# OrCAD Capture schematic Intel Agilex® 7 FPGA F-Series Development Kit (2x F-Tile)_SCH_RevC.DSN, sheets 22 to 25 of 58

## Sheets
22 PG22 AGX HPS, TEMPDIODE, DNU: size C
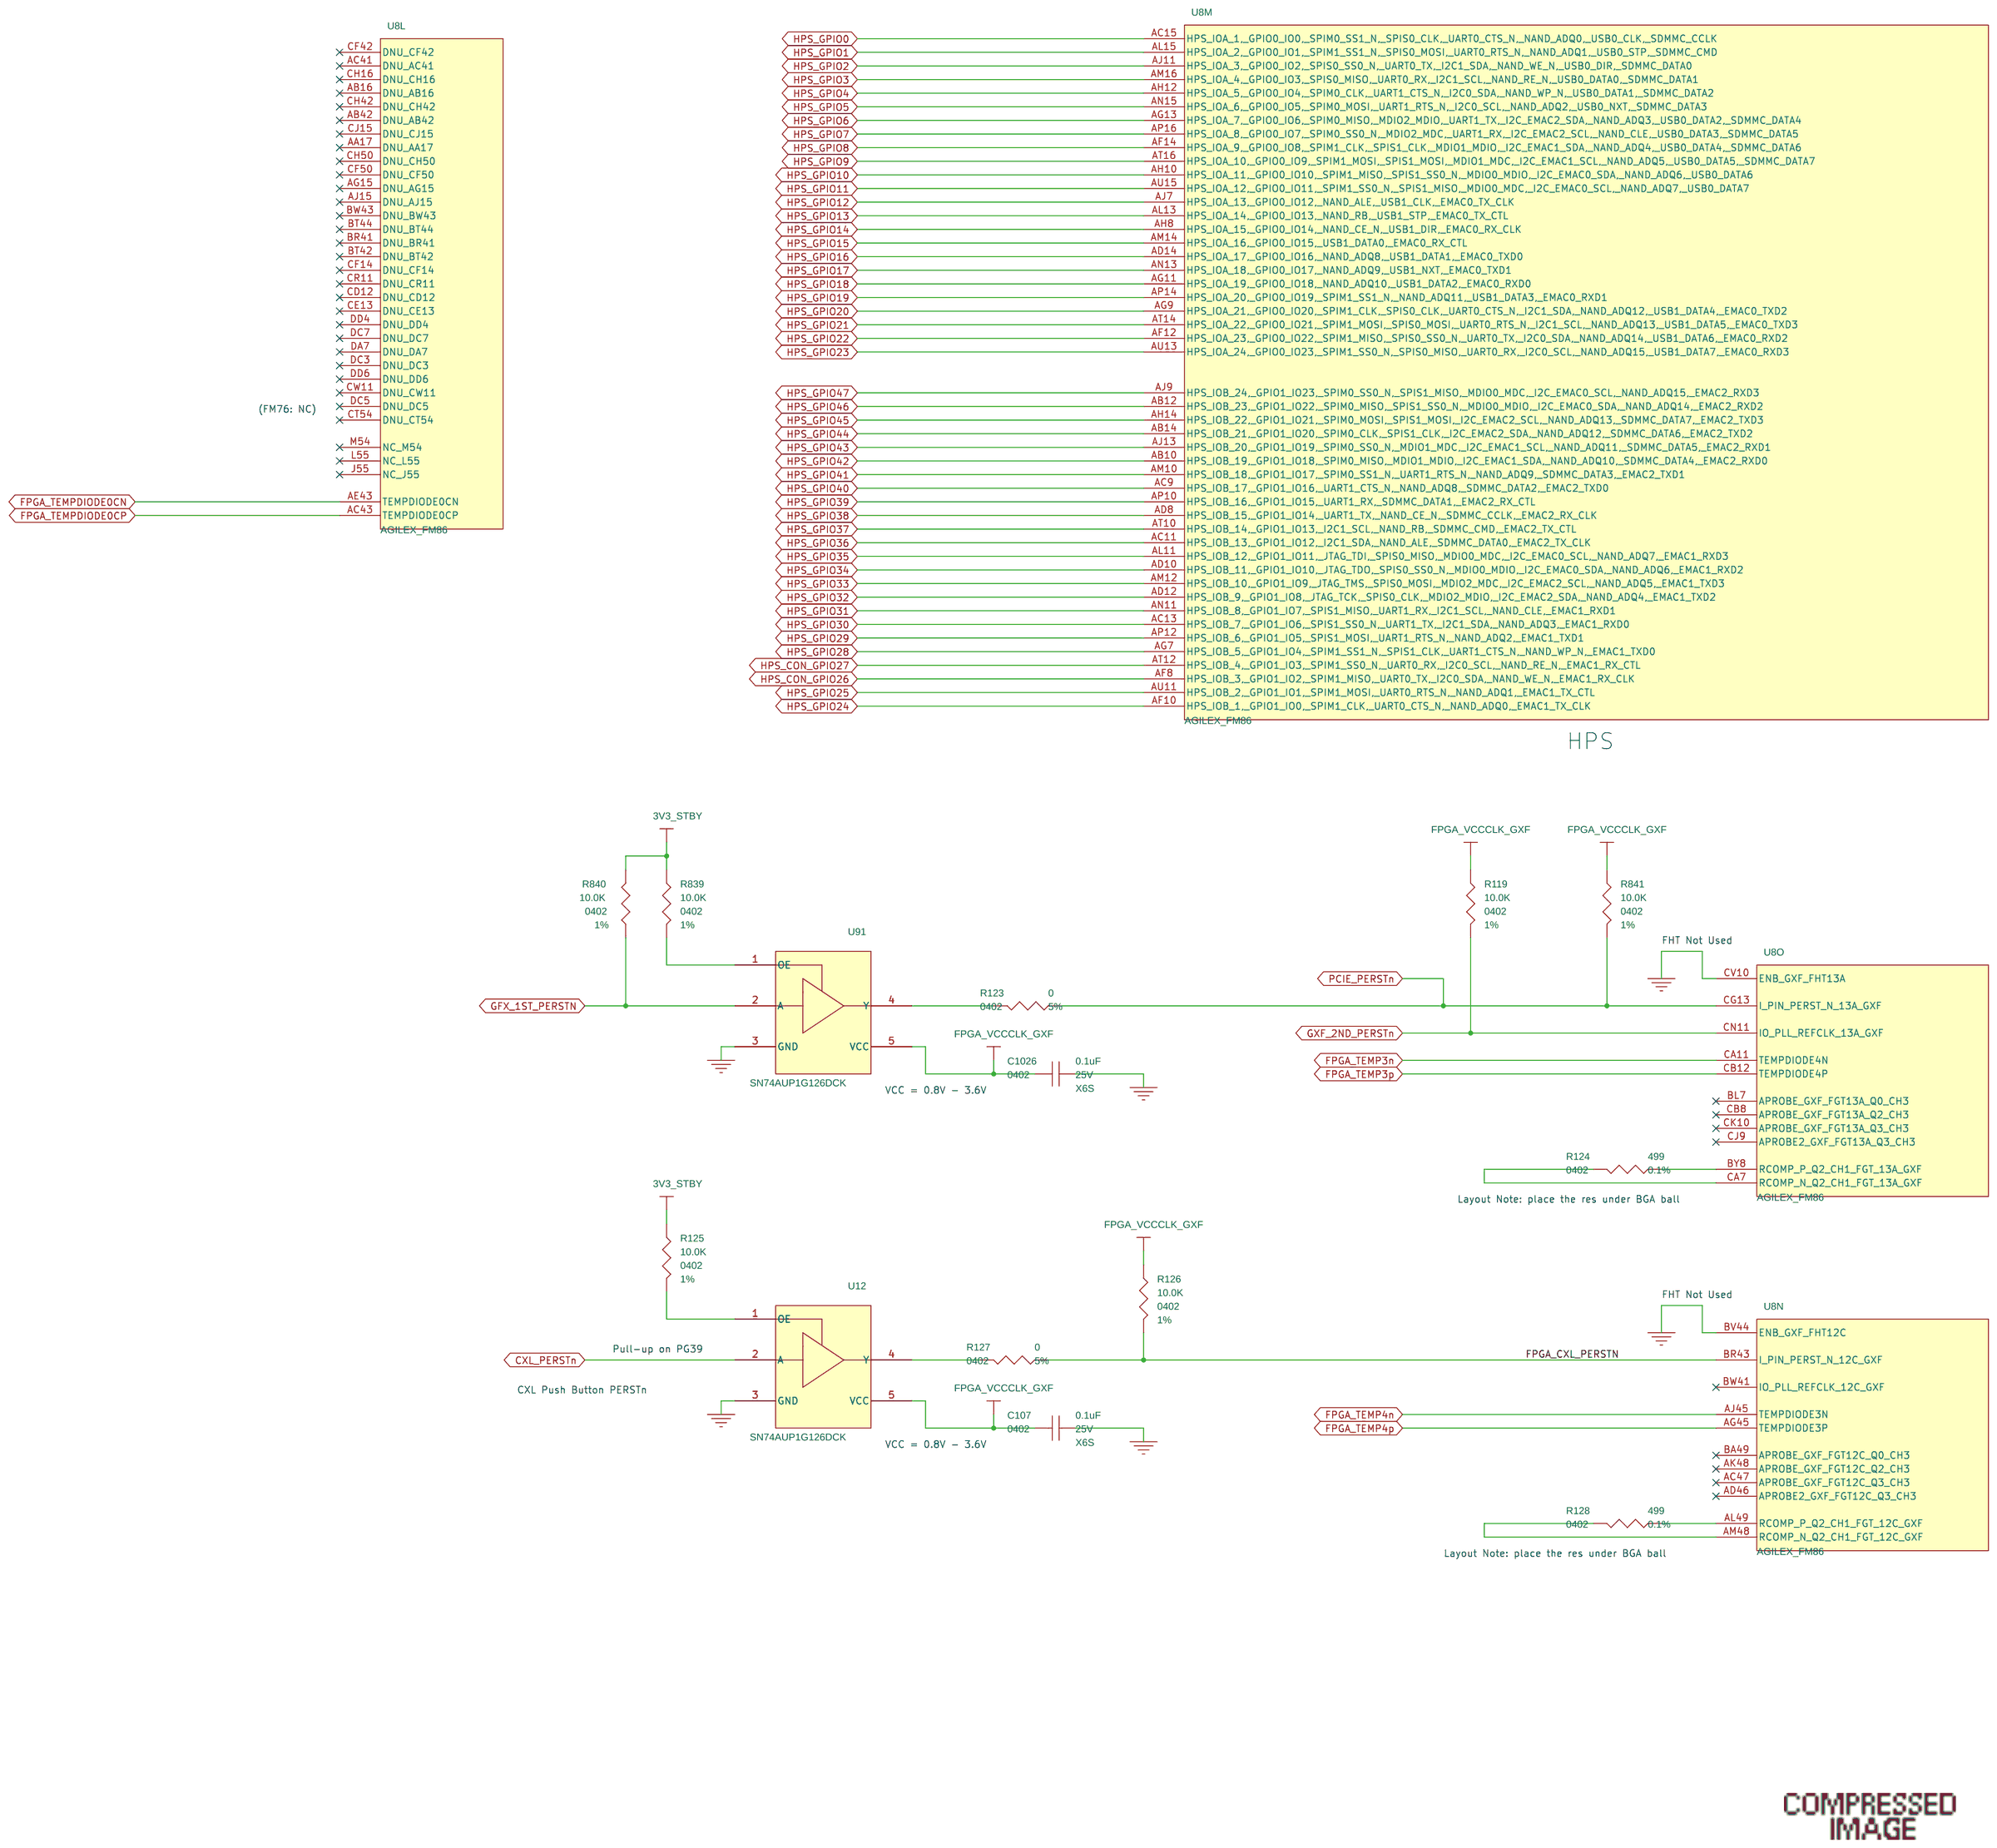
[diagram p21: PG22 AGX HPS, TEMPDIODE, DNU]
23 PG23 AGX POWER: size C
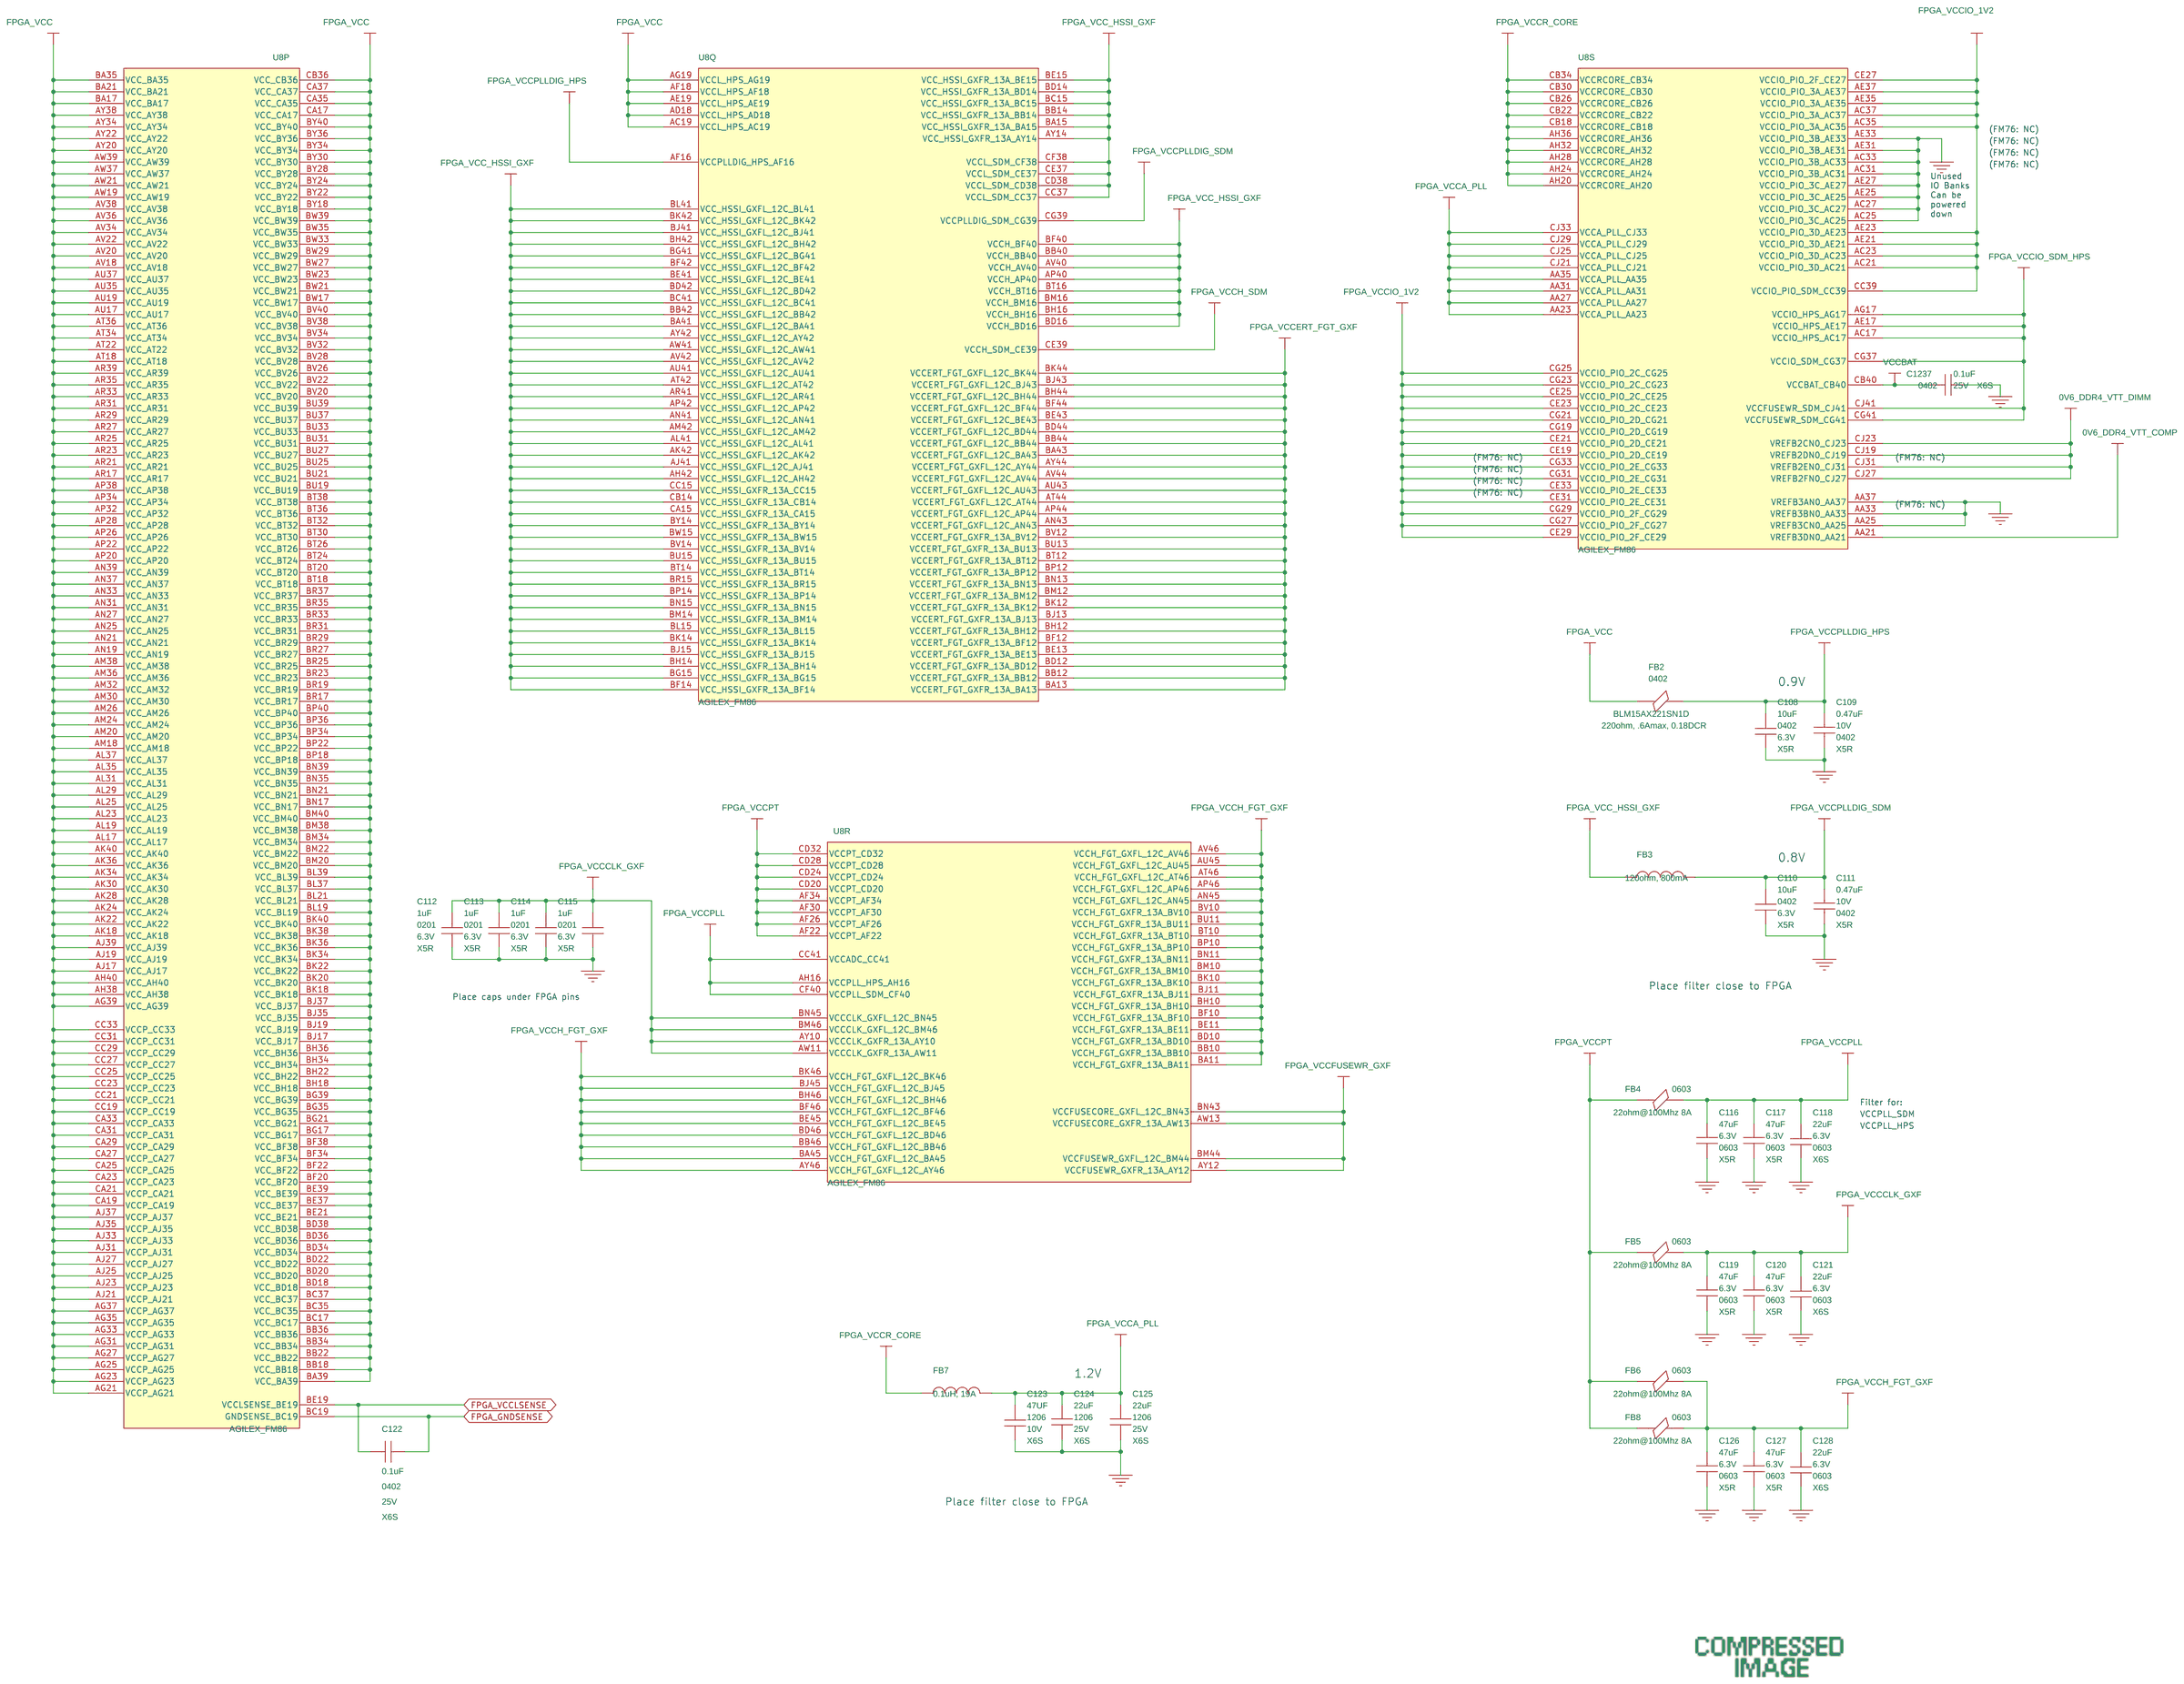
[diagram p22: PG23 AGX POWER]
24 PG24 AGX GND: size C
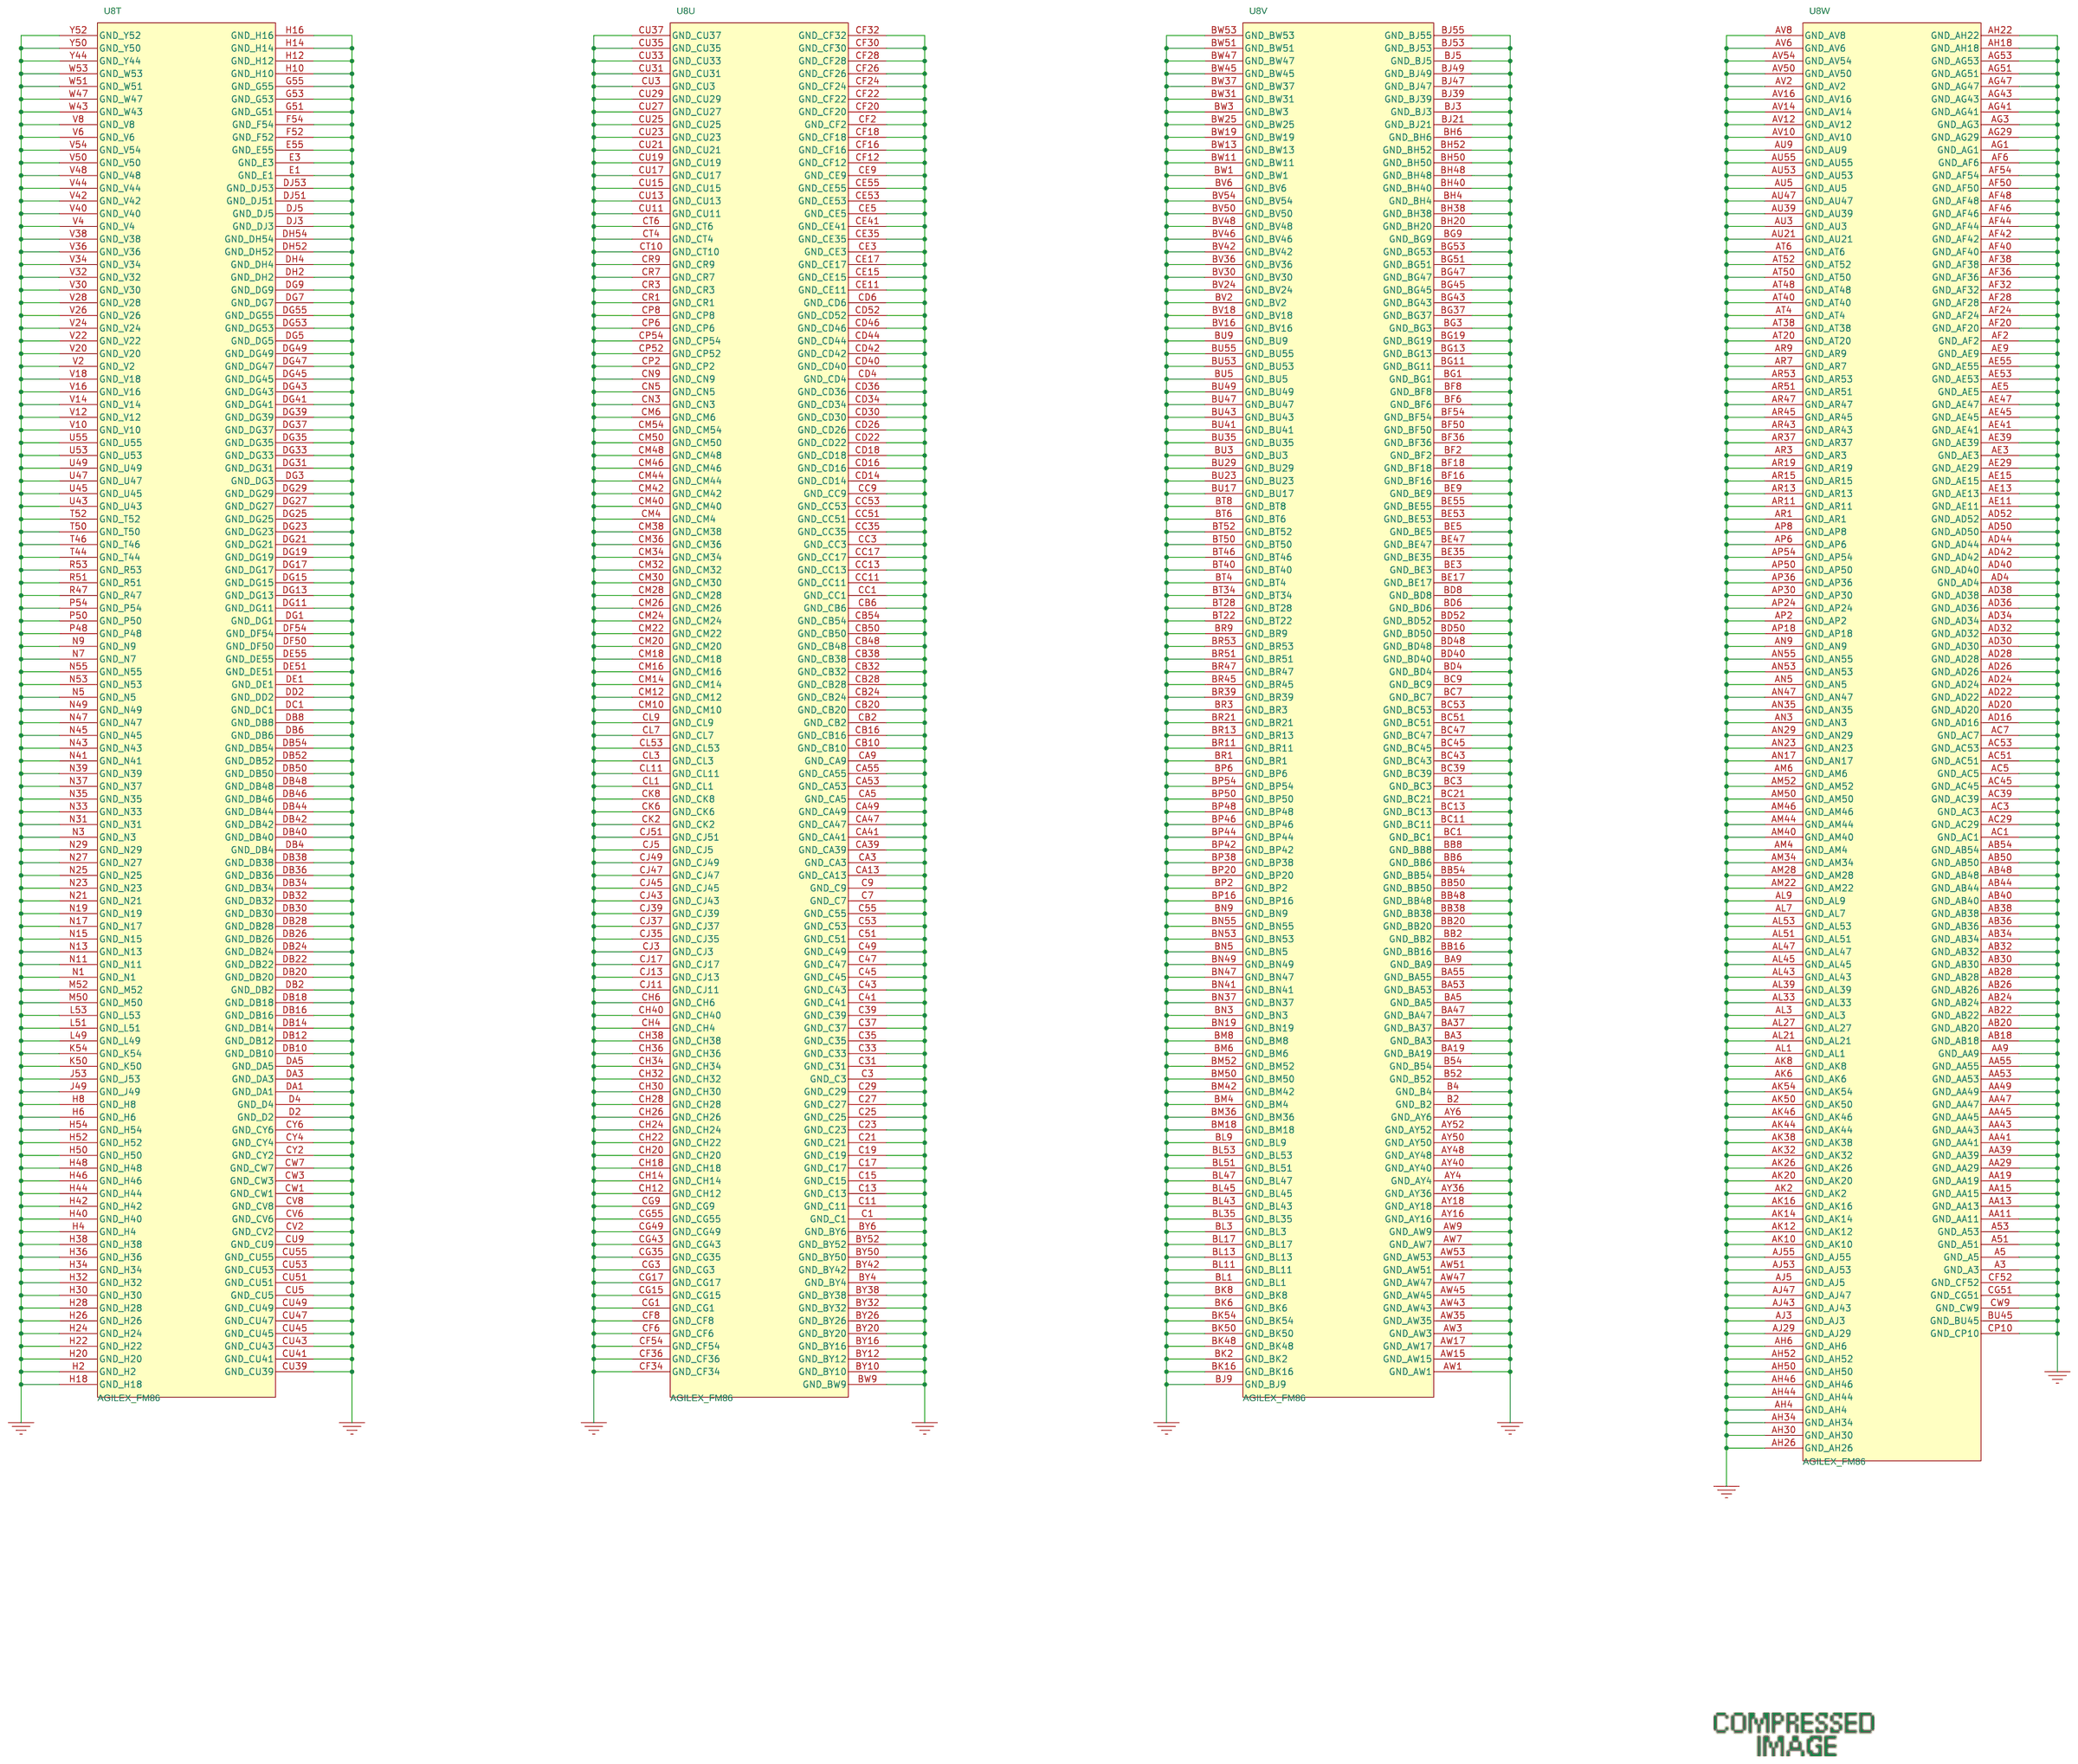
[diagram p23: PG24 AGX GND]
25 PG28 HPS DDR4 COMP1,2: size C
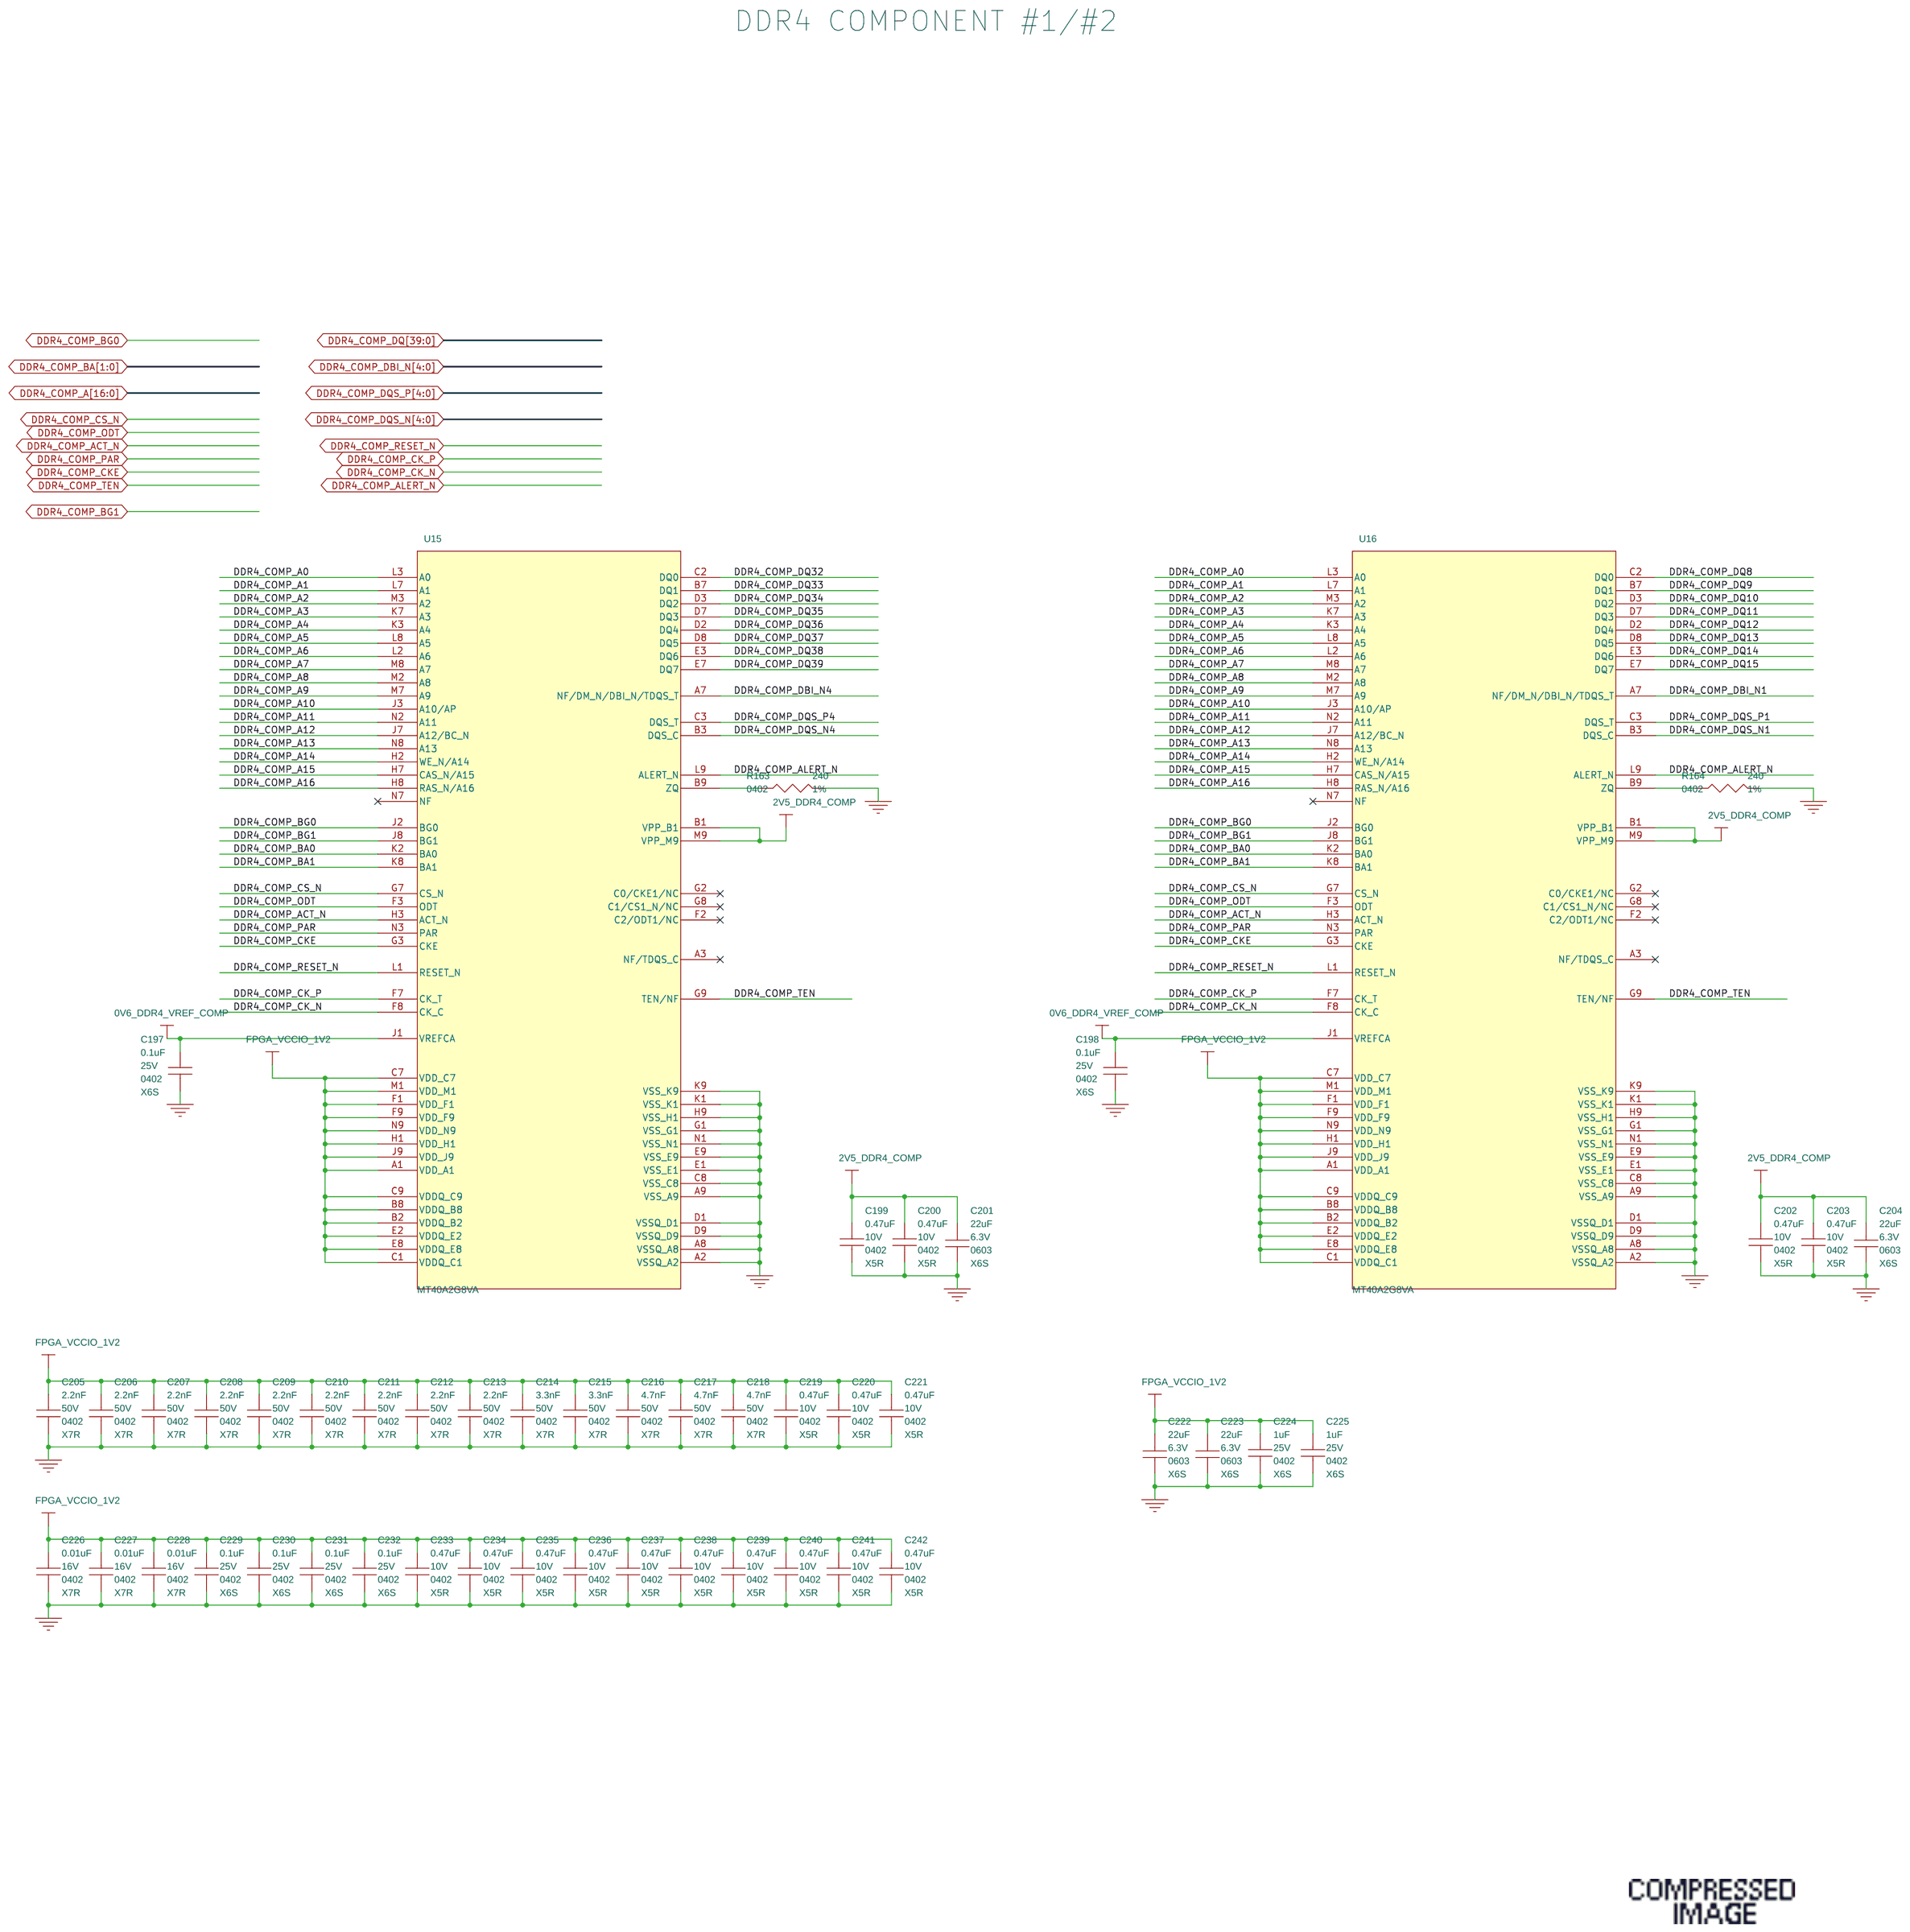
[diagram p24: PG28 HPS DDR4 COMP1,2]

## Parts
sheet PG14 AGX BANK 2E - DDR4 DIMM2
U8  AGILEX_FM86  [FBGA-2340]  (sections A,B,C,D,E,F,G,H,I,J,K,L,M,N,O,P,Q,R,S,T,U,V,W)
sheet PG22 AGX HPS, TEMPDIODE, DNU
C107  0.1uF  [0402]
C1026  0.1uF  [0402]
R119  10.0K  [0402]
R123  0  [0402]
R124  499  [0402]
R125  10.0K  [0402]
R126  10.0K  [0402]
R127  0  [0402]
R128  499  [0402]
R839  10.0K  [0402]
R840  10.0K  [0402]
R841  10.0K  [0402]
U12  SN74AUP1G126DCK  [SC70_TI]
U91  SN74AUP1G126DCK  [SC70_TI]
sheet PG23 AGX POWER
C108  10uF  [0402]
C109  0.47uF  [0402]
C110  10uF  [0402]
C111  0.47uF  [0402]
C112  1uF  [0201]
C113  1uF  [0201]
C114  1uF  [0201]
C115  1uF  [0201]
C116  47uF  [0603]
C117  47uF  [0603]
C118  22uF  [0603]
C119  47uF  [0603]
C120  47uF  [0603]
C121  22uF  [0603]
C122  0.1uF  [0402]
C123  47UF  [1206]
C124  22uF  [1206]
C125  22uF  [1206]
C126  47uF  [0603]
C127  47uF  [0603]
C128  22uF  [0603]
C1237  0.1uF  [0402]
FB2  220ohm, .6Amax, 0.18DCR  [0402]
FB3  120ohm, 800mA  [805]
FB4  22ohm@100Mhz 8A  [0603]
FB5  22ohm@100Mhz 8A  [0603]
FB6  22ohm@100Mhz 8A  [0603]
FB7  0.1uH, 19A  [SL1616A-R10MHF]
FB8  22ohm@100Mhz 8A  [0603]
sheet PG28 HPS DDR4 COMP1,2
C197  0.1uF  [0402]
C198  0.1uF  [0402]
C199  0.47uF  [0402]
C200  0.47uF  [0402]
C201  22uF  [0603]
C202  0.47uF  [0402]
C203  0.47uF  [0402]
C204  22uF  [0603]
C205  2.2nF  [0402]
C206  2.2nF  [0402]
C207  2.2nF  [0402]
C208  2.2nF  [0402]
C209  2.2nF  [0402]
C210  2.2nF  [0402]
C211  2.2nF  [0402]
C212  2.2nF  [0402]
C213  2.2nF  [0402]
C214  3.3nF  [0402]
C215  3.3nF  [0402]
C216  4.7nF  [0402]
C217  4.7nF  [0402]
C218  4.7nF  [0402]
C219  0.47uF  [0402]
C220  0.47uF  [0402]
C221  0.47uF  [0402]
C222  22uF  [0603]
C223  22uF  [0603]
C224  1uF  [0402]
C225  1uF  [0402]
C226  0.01uF  [0402]
C227  0.01uF  [0402]
C228  0.01uF  [0402]
C229  0.1uF  [0402]
C230  0.1uF  [0402]
C231  0.1uF  [0402]
C232  0.1uF  [0402]
C233  0.47uF  [0402]
C234  0.47uF  [0402]
C235  0.47uF  [0402]
C236  0.47uF  [0402]
C237  0.47uF  [0402]
C238  0.47uF  [0402]
C239  0.47uF  [0402]
C240  0.47uF  [0402]
C241  0.47uF  [0402]
C242  0.47uF  [0402]
R163  240  [0402]
R164  240  [0402]
U15  MT40A2G8VA  [FBGA-78]
U16  MT40A2G8VA  [FBGA-78]

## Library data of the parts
U8 = AGILEX_FM86: IC, FPGA, AGILEX FM86, FBGA2340; Manufacturer: Intel; Manufacturer Part Num: AGFB027R24C2E2VR0
C107 C1026 = CAP: CAP CER 0.1UF 25V X6S 0402; Dielectric: X6S; Item Num: K19434-001; LIFECYCLE_PHASE: Active; Lead Free Status: Lead Free; Manufacturer: Murata; Manufacturer Part Num: GRM155C81E104KA12D; Num Pins: 2; Part Class: CAPACITORS; RATED_VOLTAGE: 25V; RoHS Compliant: RoHS Compliant; Tolerance: 10%
R119 R125 R126 R839-R841 = RESISTOR: RES,10.0K OHMS,1.0%,1/16W, 0402; AGILE_LINK: http://sj-agile9app/Agile/PLMServlet?action=OpenEmailObject&classid=10000&objid=146548997; Item Num: K28115-001; LIFECYCLE_PHASE: Active; Lead Free Status: Yes; MFR_LIFECYCLE: Active; Manufacturer: Panasonic; Manufacturer Part Num: ERJ-2RKF1002X; Num Pins: 2; PART_SUBCLASS: RESISTORS; POWER: 1/16W; RoHS Compliant: Yes; TOLERANCE: 1%
R123 R127 = RESISTOR: RES ZERO OHM 1/16W 5% 0402 SMD; Item Num: A93549-001; Lead Free Status: No; Manufacturer: Yageo; Manufacturer Part Num: RC0402JR-070RL; Num Pins: 2; Part Class: RESISTORS; RoHS Compliant: Yes; Tolerance: 5%
R124 R128 = RESISTOR: RES 499 OHM 1/16W 0.1% 0402 SMD; Item Num: C79651-139; Manufacturer: Yageo; Manufacturer Part Num: RT0402BRE07499RL; Num Pins: 2; Part Class: RESISTORS; TOLERANCE: 0.1%
U12 U91 = SN74AUP1G126DCK: IC - LOW-POWER SINGLE BUS BUFFER GATE WITH 3-STATE OUTPUT 3.6-V I/O TOLERANT; Item Num: K14022-001; Manufacturer: Texas Instruments; Manufacturer Part Num: SN74AUP1G126DCKT
C108 C110 = CAP: CAP CER 10UF 6.3V X5R 0402; AGILE_LINK: http://sj-agile9app/Agile/PLMServlet?action=OpenEmailObject&classid=10000&objid=257560276; Item Num: K46607-001; LIFECYCLE_PHASE: Active; Lead Free Status: Lead Free; MFR_LIFECYCLE: Active; Manufacturer: Murata Electronics North America; Manufacturer Part Num: GRJ155R60J106ME11D; Num Pins: 2; PART_SUBCLASS: CAPACITORS; Part Class: CAPACITORS; RATED_VOLTAGE: 6.3V; RoHS Compliant: RoHS Compliant; TOLERANCE: 20%; Temperature Coefficient: X5R
C109 C111 C199 C200 C202 C203 C219-C221 C233-C242 = CAP: CAP - CER, .47UF, 10V, X5R, 0402; AGILE_LINK: http://sj-agile9app/Agile/PLMServlet?action=OpenEmailObject&classid=10000&objid=256989651; Item Num: H75789-001; LIFECYCLE_PHASE: Active; Lead Free Status: Lead Free; MFR_LIFECYCLE: Active; Manufacturer: Murata; Manufacturer Part Num: GRM155R61A474KE15D; Num Pins: 2; PART_SUBCLASS: CAPACITORS; Part Class: CAPACITORS; RATED_VOLTAGE: 10V; RoHS Compliant: RoHS Compliant; Temperature Coefficient: X5R; Tolerance: +80%/-20%
C112-C115 = CAP: CAP - CER 1UF 6.3V 20% X5R 0201; Item Num: C83410-013; Lead Free Status: Yes; Manufacturer: TDK; Manufacturer Part Num: C0603X5R0J105M; Num Pins: 2; Part Class: CAPACITORS; RoHS Compliant: Yes; Temperature Coefficient: X5R; Voltage: 6.3V
C116 C117 C119 C120 C126 C127 = CAP: CAP CER 47UF 6.3V X5R 0603; IPN: 602433-109; Item Num: K31624-001; MFR_LIFECYCLE: Active; Manufacturer: Murata Electronics North America; Manufacturer Part Num: GRM188R60J476ME15D; Num Pins: 2; PART_SUBCLASS: CAPACITORS; RATED_VOLTAGE: 6.3V; RoHS Compliant: RoHS Compliant; TOLERANCE: 20%; Temperature Coefficient: X5R
C118 C121 C128 C201 C204 C222 C223 = CAP: CAP CER 22UF 6.3V X6S 0603; AGILE_LINK: http://sj-agile9app/Agile/PLMServlet?action=OpenEmailObject&classid=10000&objid=257560276; Item Num: H63299-001; LIFECYCLE_PHASE: Active; Lead Free Status: Not Lead Free; MFR_LIFECYCLE: Active; Manufacturer: Murata; Manufacturer Part Num: GRM188C80J226ME15D; Num Pins: 2; PART_SUBCLASS: CAPACITORS; RATED_VOLTAGE: 6.3V; RoHS Compliant: RoHS Compliant; TOLERANCE: 20%; Temperature Coefficient: X6S
C122 C197 C198 C229-C232 C1237 = CAP: CAP CER 0.1UF 25V X6S 0402; Dielectric: X6S; IPN: K19434-001; Item Num: K19434-001; LIFECYCLE_PHASE: Active; Lead Free Status: Lead Free; MFR_LIFECYCLE: Active; Manufacturer: Murata; Manufacturer Part Num: GRM155C81E104KA12D; Num Pins: 2; PART_SUBCLASS: CAPACITORS; Part Class: CAPACITORS; RATED_VOLTAGE: 25V; RoHS Compliant: RoHS Compliant; Temperature Coefficient: X6S; Tolerance: 10%
C123 = CAP: CAP CER 47UF 10V X6S 1206; AGILE_LINK: http://sj-agile9app/Agile/PLMServlet?action=OpenEmailObject&classid=10000&objid=257560276; CAPACITANCE: 47uF; Item Num: H65935-001; LIFECYCLE_PHASE: Active; Lead Free Status: Not Lead Free; MFR_LIFECYCLE: Active; Manufacturer: TDK; Manufacturer Part Num: C3216X6S1A476M160AC; Num Pins: 2; PART_SUBCLASS: CAPACITORS; RATED_VOLTAGE: 10V; RoHS Compliant: RoHS Compliant; TOLERANCE: 20%; TYPE: X6S
C124 C125 = CAP: CAP CER 22UF 25V X6S 1206; AGILE_LINK: http://sj-agile9app/Agile/PLMServlet?action=OpenEmailObject&classid=10000&objid=257560276; Item Num: H65936-001; LIFECYCLE_PHASE: Active; Lead Free Status: Lead Free; MFR_LIFECYCLE: Active; Manufacturer: Murata; Manufacturer Part Num: GRM31CC81E226KE11L; Num Pins: 2; PART_SUBCLASS: CAPACITORS; RATED_VOLTAGE: 25V; RoHS Compliant: RoHS Compliant; TOLERANCE: 10%; Thermal Coefficient: X6S
FB2 = BEAD_FERRITE_SM: FERRITE BEAD 220 OHM 0402 1LN; Item Num: A51464-023; LIFECYCLE_PHASE: Active; MFR_LIFECYCLE: Active; Manufacturer: Murata; Manufacturer Part Num: BLM15AX221SN1D; Num Pins: 2; Part Class: Inductors; RoHS Compliant: Yes
FB3 = INDUCTOR: FERRITE BEAD 800MA 120 OHM; Item Num: K14411-001; Lead Free Status: No; Manufacturer: Steward; Manufacturer Part Num: LI0805H121R-10; Mfr Code: STED; Num Pins: 2; Part Class: Inductors; Price: 0.11; RoHS Compliant: Yes
FB4-FB6 FB8 = BEAD_FERRITE_SM: FERRITE BEAD 22 OHM 0603; Item Num: M16845-001; LIFECYCLE_PHASE: Active; MFR_LIFECYCLE: Active; Manufacturer: Murata; Manufacturer Part Num: BLM18SN220TZ1D; Num Pins: 2; PART_SUBCLASS: INDUCTORS; Part Class: Inductors; RoHS Compliant: Yes
FB7 = INDUCTOR: INDCT,0.1UH,19.0A,0.32MOHM,CUBE,SM; IPN: xxxxxx-xxx; Item Num: D92183-020; Lead Free Status: No; Manufacturer: Steward; Mfr Code: STED; Num Pins: 2; Part Class: Inductors; Price: 0.11; RoHS Compliant: Yes
C205-C213 = CAP: CAP CER 2200PF 50V 10% X7R 0402; CAPACITANCE: 2200pF; Dielectric: X7R; Item Num: K13631-001; LIFECYCLE_PHASE: Active; Lead Free Status: Lead Free; Manufacturer: TDK; Manufacturer Part Num: CGJ2B2X7R1E222K050BA; Num Pins: 2; PART_SUBCLASS: CAPACITORS; Part Class: CAPACITORS; RATED_VOLTAGE: 50V; RoHS Compliant: RoHS Compliant; TOLERANCE: +/-10%; Temperature Coefficient: X7R
C214 C215 = CAP: CAP, CERAMIC, 3300PF, 10%, 50V, X7R, 0402; Item Num: K13754-001; LIFECYCLE_PHASE: Active; Lead Free Status: Lead Free; MFR_LIFECYCLE: Active; Manufacturer: Murata; Manufacturer Part Num: GRM155F51H332ZA01x; Num Pins: 2; PART_SUBCLASS: CAPACITORS; RATED_VOLTAGE: 50V; RoHS Compliant: RoHS Compliant; TOLERANCE: +/-10%; Temperature Coefficient: X7R
C216-C218 = CAP: CAP - CER 4700PF 50V 10% X7R 0402; AGILE_LINK: http://sj-agile9app/Agile/PLMServlet?action=OpenEmailObject&classid=10000&objid=215384813; Item Num: G24897-001; LIFECYCLE_PHASE: Active; Lead Free Status: Lead Free; MFR_LIFECYCLE: Active; Manufacturer: Murata; Manufacturer Part Num: GRM155R71H472KA01D; Num Pins: 2; PACKAGING: Tape & Reel (TR); PART_SUBCLASS: CAPACITORS; RATED_VOLTAGE: 50V; RoHS Compliant: RoHS Compliant; Supplier Part Num: GRM155R71H472KA01D; Temperature Coefficient: X7R; Tolerance: 10%
C224 C225 = CAP: CAP CER 1UF 25V X6S 0402; Item Num: H81594-001; Lead Free Status: Yes; Manufacturer: Murata; Manufacturer Part Num: GRM155C81E105KE11D; Num Pins: 2; Part Class: CAPACITORS; RATED_VOLTAGE: 25V; RoHS Compliant: Yes; Temperature Coefficient: X6S; Voltage: 25V
C226-C228 = CAP: CAP, CER .01UF 16V X7R 0402; Item Num: A36096-007; Lead Free Status: Yes; Manufacturer: Murata; Manufacturer Part Num: GRM155R71C103KA01D; Manufacturer's Part No.: GRM155R71C103KA01D; Num Pins: 2; Part Class: CAPACITORS; RoHS Compliant: Yes; Temperature Coefficient: X7R; Tolerance: 10%; Voltage: 16V
R163 R164 = RESISTOR: RES - 240 OHM, 1/16W, 1%, 0402 SMD; Item Num: K15783-001; LIFECYCLE_PHASE: Active; Lead Free Status: Yes; MFR_LIFECYCLE: Active; Manufacturer: Panasonic; Manufacturer Part Num: ERJ-2RKF2400X; Num Pins: 2; PART_SUBCLASS: RESISTORS; RoHS Compliant: Yes; Tolerance: 1%
U15 U16 = MT40A2G8VA: IC, DDR4, DRAM, 2Gx8, FPGA, 78-BALL; Item Num: K74985-002; Manufacturer: Micron; Manufacturer Part Num: MT40A2G8JC-062E IT:E

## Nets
0V6_DDR4_VREF_COMP: C197.1 C198.1 U15.J1(VREFCA) U16.J1(VREFCA) ; also on sheet 26 27 54
0V6_DDR4_VTT_COMP: U8.AA21(VREFB3DN0) ; also on sheet 27 54
0V6_DDR4_VTT_DIMM: U8.CJ19(VREFB2DN0) U8.CJ23(VREFB2CN0) U8.CJ27(VREFB2FN0) U8.CJ31(VREFB2EN0) ; also on sheet 54 55 56
2V5_DDR4_COMP: C199.1 C200.1 C201.2 C202.1 C203.1 C204.2 U15.B1(VPP) U15.M9(VPP) U16.B1(VPP) U16.M9(VPP) ; also on sheet 26 27 54
3V3_STBY: R125.2 R839.2 R840.2 ; also on sheet 8 10 16 28 32 34 36 37 38 40 41 48 49 50 51 52 53 54 58
GND: C107.1 C108.1 C109.2 C110.1 C111.2 C112.1 C113.1 C114.1 C115.1 C116.2 C117.2 C118.1 C119.2 C120.2 C121.1 C123.1 C124.2 C125.2 C126.2 C127.2 C128.1 C197.2 C198.2 C199.2 C200.2 C201.1 C202.2 C203.2 C204.1 C205.2 C206.2 C207.2 C208.2 C209.2 C210.2 C211.2 C212.2 C213.2 C214.2 C215.2 C216.2 C217.2 C218.2 C219.2 C220.2 C221.2 C222.1 C223.1 C224.2 C225.2 C226.2 C227.2 C228.2 C229.2 C230.2 C231.2 C232.2 C233.2 C234.2 C235.2 C236.2 C237.2 C238.2 C239.2 C240.2 C241.2 C242.2 C1026.1 C1237.1 R163.1 R164.1 U8.A3(GND) U8.A5(GND) U8.A51(GND) U8.A53(GND) U8.AA9(GND) U8.AA11(GND) U8.AA13(GND) U8.AA15(GND) U8.AA19(GND) U8.AA25(VREFB3CN0) U8.AA29(GND) U8.AA33(VREFB3BN0) U8.AA37(VREFB3AN0) U8.AA39(GND) U8.AA41(GND) U8.AA43(GND) U8.AA45(GND) U8.AA47(GND) U8.AA49(GND) U8.AA53(GND) U8.AA55(GND) U8.AB18(GND) U8.AB20(GND) U8.AB22(GND) U8.AB24(GND) U8.AB26(GND) U8.AB28(GND) U8.AB30(GND) U8.AB32(GND) U8.AB34(GND) U8.AB36(GND) U8.AB38(GND) U8.AB40(GND) U8.AB44(GND) U8.AB48(GND) U8.AB50(GND) U8.AB54(GND) U8.AC1(GND) U8.AC3(GND) U8.AC5(GND) U8.AC7(GND) U8.AC25(VCCIO_PIO_3C) U8.AC27(VCCIO_PIO_3C) U8.AC29(GND) U8.AC31(VCCIO_PIO_3B) U8.AC33(VCCIO_PIO_3B) U8.AC39(GND) U8.AC45(GND) U8.AC51(GND) U8.AC53(GND) U8.AD4(GND) U8.AD16(GND) U8.AD20(GND) U8.AD22(GND) U8.AD24(GND) U8.AD26(GND) U8.AD28(GND) U8.AD30(GND) U8.AD32(GND) U8.AD34(GND) U8.AD36(GND) U8.AD38(GND) U8.AD40(GND) U8.AD42(GND) U8.AD44(GND) U8.AD50(GND) U8.AD52(GND) U8.AE3(GND) U8.AE5(GND) U8.AE9(GND) U8.AE11(GND) U8.AE13(GND) U8.AE15(GND) U8.AE25(VCCIO_PIO_3C) U8.AE27(VCCIO_PIO_3C) U8.AE29(GND) U8.AE31(VCCIO_PIO_3B) U8.AE33(VCCIO_PIO_3B) U8.AE39(GND) U8.AE41(GND) U8.AE45(GND) U8.AE47(GND) U8.AE53(GND) U8.AE55(GND) U8.AF2(GND) U8.AF6(GND) U8.AF20(GND) U8.AF24(GND) U8.AF28(GND) U8.AF32(GND) U8.AF36(GND) U8.AF38(GND) U8.AF40(GND) U8.AF42(GND) U8.AF44(GND) U8.AF46(GND) U8.AF48(GND) U8.AF50(GND) U8.AF54(GND) U8.AG1(GND) U8.AG3(GND) U8.AG29(GND) U8.AG41(GND) U8.AG43(GND) U8.AG47(GND) U8.AG51(GND) U8.AG53(GND) U8.AH4(GND) U8.AH6(GND) U8.AH18(GND) U8.AH22(GND) U8.AH26(GND) U8.AH30(GND) U8.AH34(GND) U8.AH44(GND) U8.AH46(GND) U8.AH50(GND) U8.AH52(GND) U8.AJ3(GND) U8.AJ5(GND) U8.AJ29(GND) U8.AJ43(GND) U8.AJ47(GND) U8.AJ53(GND) U8.AJ55(GND) U8.AK2(GND) U8.AK6(GND) U8.AK8(GND) U8.AK10(GND) U8.AK12(GND) U8.AK14(GND) U8.AK16(GND) U8.AK20(GND) U8.AK26(GND) U8.AK32(GND) U8.AK38(GND) U8.AK44(GND) U8.AK46(GND) U8.AK50(GND) U8.AK54(GND) U8.AL1(GND) U8.AL3(GND) U8.AL7(GND) U8.AL9(GND) U8.AL21(GND) U8.AL27(GND) U8.AL33(GND) U8.AL39(GND) U8.AL43(GND) U8.AL45(GND) U8.AL47(GND) U8.AL51(GND) U8.AL53(GND) U8.AM4(GND) U8.AM6(GND) U8.AM22(GND) U8.AM28(GND) U8.AM34(GND) U8.AM40(GND) U8.AM44(GND) U8.AM46(GND) U8.AM50(GND) U8.AM52(GND) U8.AN3(GND) U8.AN5(GND) U8.AN9(GND) U8.AN17(GND) U8.AN23(GND) U8.AN29(GND) U8.AN35(GND) U8.AN47(GND) U8.AN53(GND) U8.AN55(GND) U8.AP2(GND) U8.AP6(GND) U8.AP8(GND) U8.AP18(GND) U8.AP24(GND) U8.AP30(GND) U8.AP36(GND) U8.AP50(GND) U8.AP54(GND) U8.AR1(GND) U8.AR3(GND) U8.AR7(GND) U8.AR9(GND) U8.AR11(GND) U8.AR13(GND) U8.AR15(GND) U8.AR19(GND) U8.AR37(GND) U8.AR43(GND) U8.AR45(GND) U8.AR47(GND) U8.AR51(GND) U8.AR53(GND) U8.AT4(GND) U8.AT6(GND) U8.AT20(GND) U8.AT38(GND) U8.AT40(GND) U8.AT48(GND) U8.AT50(GND) U8.AT52(GND) U8.AU3(GND) U8.AU5(GND) U8.AU9(GND) U8.AU21(GND) U8.AU39(GND) U8.AU47(GND) U8.AU53(GND) U8.AU55(GND) U8.AV2(GND) U8.AV6(GND) U8.AV8(GND) U8.AV10(GND) U8.AV12(GND) U8.AV14(GND) U8.AV16(GND) U8.AV50(GND) U8.AV54(GND) U8.AW1(GND) U8.AW3(GND) U8.AW7(GND) U8.AW9(GND) U8.AW15(GND) U8.AW17(GND) U8.AW35(GND) U8.AW43(GND) U8.AW45(GND) U8.AW47(GND) U8.AW51(GND) U8.AW53(GND) U8.AY4(GND) U8.AY6(GND) U8.AY16(GND) U8.AY18(GND) U8.AY36(GND) U8.AY40(GND) U8.AY48(GND) U8.AY50(GND) U8.AY52(GND) U8.B2(GND) U8.B4(GND) U8.B52(GND) U8.B54(GND) U8.BA3(GND) U8.BA5(GND) U8.BA9(GND) U8.BA19(GND) U8.BA37(GND) U8.BA47(GND) U8.BA53(GND) U8.BA55(GND) U8.BB2(GND) U8.BB6(GND) U8.BB8(GND) U8.BB16(GND) U8.BB20(GND) U8.BB38(GND) U8.BB48(GND) U8.BB50(GND) U8.BB54(GND) U8.BC1(GND) U8.BC3(GND) U8.BC7(GND) U8.BC9(GND) U8.BC11(GND) U8.BC13(GND) U8.BC21(GND) U8.BC39(GND) U8.BC43(GND) U8.BC45(GND) U8.BC47(GND) U8.BC51(GND) U8.BC53(GND) U8.BD4(GND) U8.BD6(GND) U8.BD8(GND) U8.BD40(GND) U8.BD48(GND) U8.BD50(GND) U8.BD52(GND) U8.BE3(GND) U8.BE5(GND) U8.BE9(GND) U8.BE17(GND) U8.BE35(GND) U8.BE47(GND) U8.BE53(GND) U8.BE55(GND) U8.BF2(GND) U8.BF6(GND) U8.BF8(GND) U8.BF16(GND) U8.BF18(GND) U8.BF36(GND) U8.BF50(GND) U8.BF54(GND) U8.BG1(GND) U8.BG3(GND) U8.BG9(GND) U8.BG11(GND) U8.BG13(GND) U8.BG19(GND) U8.BG37(GND) U8.BG43(GND) U8.BG45(GND) U8.BG47(GND) U8.BG51(GND) U8.BG53(GND) U8.BH4(GND) U8.BH6(GND) U8.BH20(GND) U8.BH38(GND) U8.BH40(GND) U8.BH48(GND) U8.BH50(GND) U8.BH52(GND) U8.BJ3(GND) U8.BJ5(GND) U8.BJ9(GND) U8.BJ21(GND) U8.BJ39(GND) U8.BJ47(GND) U8.BJ49(GND) U8.BJ53(GND) U8.BJ55(GND) U8.BK2(GND) U8.BK6(GND) U8.BK8(GND) U8.BK16(GND) U8.BK48(GND) U8.BK50(GND) U8.BK54(GND) U8.BL1(GND) U8.BL3(GND) U8.BL9(GND) U8.BL11(GND) U8.BL13(GND) U8.BL17(GND) U8.BL35(GND) U8.BL43(GND) U8.BL45(GND) U8.BL47(GND) U8.BL51(GND) U8.BL53(GND) U8.BM4(GND) U8.BM6(GND) U8.BM8(GND) U8.BM18(GND) U8.BM36(GND) U8.BM42(GND) U8.BM50(GND) U8.BM52(GND) U8.BN3(GND) U8.BN5(GND) U8.BN9(GND) U8.BN19(GND) U8.BN37(GND) U8.BN41(GND) U8.BN47(GND) U8.BN49(GND) U8.BN53(GND) U8.BN55(GND) U8.BP2(GND) U8.BP6(GND) U8.BP16(GND) U8.BP20(GND) U8.BP38(GND) U8.BP42(GND) U8.BP44(GND) U8.BP46(GND) U8.BP48(GND) U8.BP50(GND) U8.BP54(GND) U8.BR1(GND) U8.BR3(GND) U8.BR9(GND) U8.BR11(GND) U8.BR13(GND) U8.BR21(GND) U8.BR39(GND) U8.BR45(GND) U8.BR47(GND) U8.BR51(GND) U8.BR53(GND) U8.BT4(GND) U8.BT6(GND) U8.BT8(GND) U8.BT22(GND) U8.BT28(GND) U8.BT34(GND) U8.BT40(GND) U8.BT46(GND) U8.BT50(GND) U8.BT52(GND) U8.BU3(GND) U8.BU5(GND) U8.BU9(GND) U8.BU17(GND) U8.BU23(GND) U8.BU29(GND) U8.BU35(GND) U8.BU41(GND) U8.BU43(GND) U8.BU45(GND) U8.BU47(GND) U8.BU49(GND) U8.BU53(GND) U8.BU55(GND) U8.BV2(GND) U8.BV6(GND) U8.BV16(GND) U8.BV18(GND) U8.BV24(GND) U8.BV30(GND) U8.BV36(GND) U8.BV42(GND) U8.BV44(ENB_GXF_FHT12C) U8.BV46(GND) U8.BV48(GND) U8.BV50(GND) U8.BV54(GND) U8.BW1(GND) U8.BW3(GND) U8.BW9(GND) U8.BW11(GND) U8.BW13(GND) U8.BW19(GND) U8.BW25(GND) U8.BW31(GND) U8.BW37(GND) U8.BW45(GND) U8.BW47(GND) U8.BW51(GND) U8.BW53(GND) U8.BY4(GND) U8.BY6(GND) U8.BY10(GND) U8.BY12(GND) U8.BY16(GND) U8.BY20(GND) U8.BY26(GND) U8.BY32(GND) U8.BY38(GND) U8.BY42(GND) U8.BY50(GND) U8.BY52(GND) U8.C1(GND) U8.C3(GND) U8.C7(GND) U8.C9(GND) U8.C11(GND) U8.C13(GND) U8.C15(GND) U8.C17(GND) U8.C19(GND) U8.C21(GND) U8.C23(GND) U8.C25(GND) U8.C27(GND) U8.C29(GND) U8.C31(GND) U8.C33(GND) U8.C35(GND) U8.C37(GND) U8.C39(GND) U8.C41(GND) U8.C43(GND) U8.C45(GND) U8.C47(GND) U8.C49(GND) U8.C51(GND) U8.C53(GND) U8.C55(GND) U8.CA3(GND) U8.CA5(GND) U8.CA9(GND) U8.CA13(GND) U8.CA39(GND) U8.CA41(GND) U8.CA47(GND) U8.CA49(GND) U8.CA53(GND) U8.CA55(GND) U8.CB2(GND) U8.CB6(GND) U8.CB10(GND) U8.CB16(GND) U8.CB20(GND) U8.CB24(GND) U8.CB28(GND) U8.CB32(GND) U8.CB38(GND) U8.CB48(GND) U8.CB50(GND) U8.CB54(GND) U8.CC1(GND) U8.CC3(GND) U8.CC9(GND) U8.CC11(GND) U8.CC13(GND) U8.CC17(GND) U8.CC35(GND) U8.CC51(GND) U8.CC53(GND) U8.CD4(GND) U8.CD6(GND) U8.CD14(GND) U8.CD16(GND) U8.CD18(GND) U8.CD22(GND) U8.CD26(GND) U8.CD30(GND) U8.CD34(GND) U8.CD36(GND) U8.CD40(GND) U8.CD42(GND) U8.CD44(GND) U8.CD46(GND) U8.CD52(GND) U8.CE3(GND) U8.CE5(GND) U8.CE9(GND) U8.CE11(GND) U8.CE15(GND) U8.CE17(GND) U8.CE35(GND) U8.CE41(GND) U8.CE53(GND) U8.CE55(GND) U8.CF2(GND) U8.CF6(GND) U8.CF8(GND) U8.CF12(GND) U8.CF16(GND) U8.CF18(GND) U8.CF20(GND) U8.CF22(GND) U8.CF24(GND) U8.CF26(GND) U8.CF28(GND) U8.CF30(GND) U8.CF32(GND) U8.CF34(GND) U8.CF36(GND) U8.CF52(GND) U8.CF54(GND) U8.CG1(GND) U8.CG3(GND) U8.CG9(GND) U8.CG15(GND) U8.CG17(GND) U8.CG35(GND) U8.CG43(GND) U8.CG49(GND) U8.CG51(GND) U8.CG55(GND) U8.CH4(GND) U8.CH6(GND) U8.CH12(GND) U8.CH14(GND) U8.CH18(GND) U8.CH20(GND) U8.CH22(GND) U8.CH24(GND) U8.CH26(GND) U8.CH28(GND) U8.CH30(GND) U8.CH32(GND) U8.CH34(GND) U8.CH36(GND) U8.CH38(GND) U8.CH40(GND) U8.CJ3(GND) U8.CJ5(GND) U8.CJ11(GND) U8.CJ13(GND) U8.CJ17(GND) U8.CJ35(GND) U8.CJ37(GND) U8.CJ39(GND) U8.CJ43(GND) U8.CJ45(GND) U8.CJ47(GND) U8.CJ49(GND) U8.CJ51(GND) U8.CK2(GND) U8.CK6(GND) U8.CK8(GND) U8.CL1(GND) U8.CL3(GND) U8.CL7(GND) U8.CL9(GND) U8.CL11(GND) U8.CL53(GND) U8.CM4(GND) U8.CM6(GND) U8.CM10(GND) U8.CM12(GND) U8.CM14(GND) U8.CM16(GND) U8.CM18(GND) U8.CM20(GND) U8.CM22(GND) U8.CM24(GND) U8.CM26(GND) U8.CM28(GND) U8.CM30(GND) U8.CM32(GND) U8.CM34(GND) U8.CM36(GND) U8.CM38(GND) U8.CM40(GND) U8.CM42(GND) U8.CM44(GND) U8.CM46(GND) U8.CM48(GND) U8.CM50(GND) U8.CM54(GND) U8.CN3(GND) U8.CN5(GND) U8.CN9(GND) U8.CP2(GND) U8.CP6(GND) U8.CP8(GND) U8.CP10(GND) U8.CP52(GND) U8.CP54(GND) U8.CR1(GND) U8.CR3(GND) U8.CR7(GND) U8.CR9(GND) U8.CT4(GND) U8.CT6(GND) U8.CT10(GND) U8.CU3(GND) U8.CU5(GND) U8.CU9(GND) U8.CU11(GND) U8.CU13(GND) U8.CU15(GND) U8.CU17(GND) U8.CU19(GND) U8.CU21(GND) U8.CU23(GND) U8.CU25(GND) U8.CU27(GND) U8.CU29(GND) U8.CU31(GND) U8.CU33(GND) U8.CU35(GND) U8.CU37(GND) U8.CU39(GND) U8.CU41(GND) U8.CU43(GND) U8.CU45(GND) U8.CU47(GND) U8.CU49(GND) U8.CU51(GND) U8.CU53(GND) U8.CU55(GND) U8.CV2(GND) U8.CV6(GND) U8.CV8(GND) U8.CV10(ENB_GXF_FHT13A) U8.CW1(GND) U8.CW3(GND) U8.CW7(GND) U8.CW9(GND) U8.CY2(GND) U8.CY4(GND) U8.CY6(GND) U8.D2(GND) U8.D4(GND) U8.DA1(GND) U8.DA3(GND) U8.DA5(GND) U8.DB2(GND) U8.DB4(GND) U8.DB6(GND) U8.DB8(GND) U8.DB10(GND) U8.DB12(GND) U8.DB14(GND) U8.DB16(GND) U8.DB18(GND) U8.DB20(GND) U8.DB22(GND) U8.DB24(GND) U8.DB26(GND) U8.DB28(GND) U8.DB30(GND) U8.DB32(GND) U8.DB34(GND) U8.DB36(GND) U8.DB38(GND) U8.DB40(GND) U8.DB42(GND) U8.DB44(GND) U8.DB46(GND) U8.DB48(GND) U8.DB50(GND) U8.DB52(GND) U8.DB54(GND) U8.DC1(GND) U8.DD2(GND) U8.DE1(GND) U8.DE51(GND) U8.DE55(GND) U8.DF50(GND) U8.DF54(GND) U8.DG1(GND) U8.DG3(GND) U8.DG5(GND) U8.DG7(GND) U8.DG9(GND) U8.DG11(GND) U8.DG13(GND) U8.DG15(GND) U8.DG17(GND) U8.DG19(GND) U8.DG21(GND) U8.DG23(GND) U8.DG25(GND) U8.DG27(GND) U8.DG29(GND) U8.DG31(GND) U8.DG33(GND) U8.DG35(GND) U8.DG37(GND) U8.DG39(GND) U8.DG41(GND) U8.DG43(GND) U8.DG45(GND) U8.DG47(GND) U8.DG49(GND) U8.DG53(GND) U8.DG55(GND) U8.DH2(GND) U8.DH4(GND) U8.DH52(GND) U8.DH54(GND) U8.DJ3(GND) U8.DJ5(GND) U8.DJ51(GND) U8.DJ53(GND) U8.E1(GND) U8.E3(GND) U8.E55(GND) U8.F52(GND) U8.F54(GND) U8.G51(GND) U8.G53(GND) U8.G55(GND) U8.H2(GND) U8.H4(GND) U8.H6(GND) U8.H8(GND) U8.H10(GND) U8.H12(GND) U8.H14(GND) U8.H16(GND) U8.H18(GND) U8.H20(GND) U8.H22(GND) U8.H24(GND) U8.H26(GND) U8.H28(GND) U8.H30(GND) U8.H32(GND) U8.H34(GND) U8.H36(GND) U8.H38(GND) U8.H40(GND) U8.H42(GND) U8.H44(GND) U8.H46(GND) U8.H48(GND) U8.H50(GND) U8.H52(GND) U8.H54(GND) U8.J49(GND) U8.J53(GND) U8.K50(GND) U8.K54(GND) U8.L49(GND) U8.L51(GND) U8.L53(GND) U8.M50(GND) U8.M52(GND) U8.N1(GND) U8.N3(GND) U8.N5(GND) U8.N7(GND) U8.N9(GND) U8.N11(GND) U8.N13(GND) U8.N15(GND) U8.N17(GND) U8.N19(GND) U8.N21(GND) U8.N23(GND) U8.N25(GND) U8.N27(GND) U8.N29(GND) U8.N31(GND) U8.N33(GND) U8.N35(GND) U8.N37(GND) U8.N39(GND) U8.N41(GND) U8.N43(GND) U8.N45(GND) U8.N47(GND) U8.N49(GND) U8.N53(GND) U8.N55(GND) U8.P48(GND) U8.P50(GND) U8.P54(GND) U8.R47(GND) U8.R51(GND) U8.R53(GND) U8.T44(GND) U8.T46(GND) U8.T50(GND) U8.T52(GND) U8.U43(GND) U8.U45(GND) U8.U47(GND) U8.U49(GND) U8.U53(GND) U8.U55(GND) U8.V2(GND) U8.V4(GND) U8.V6(GND) U8.V8(GND) U8.V10(GND) U8.V12(GND) U8.V14(GND) U8.V16(GND) U8.V18(GND) U8.V20(GND) U8.V22(GND) U8.V24(GND) U8.V26(GND) U8.V28(GND) U8.V30(GND) U8.V32(GND) U8.V34(GND) U8.V36(GND) U8.V38(GND) U8.V40(GND) U8.V42(GND) U8.V44(GND) U8.V48(GND) U8.V50(GND) U8.V54(GND) U8.W43(GND) U8.W47(GND) U8.W51(GND) U8.W53(GND) U8.Y44(GND) U8.Y50(GND) U8.Y52(GND) U12.3(GND) U15.A2(VSSQ) U15.A8(VSSQ) U15.A9(VSS) U15.C8(VSS) U15.D1(VSSQ) U15.D9(VSSQ) U15.E1(VSS) U15.E9(VSS) U15.G1(VSS) U15.H9(VSS_H1) U15.K1(VSS) U15.K9(VSS) U15.N1(VSS) U16.A2(VSSQ) U16.A8(VSSQ) U16.A9(VSS) U16.C8(VSS) U16.D1(VSSQ) U16.D9(VSSQ) U16.E1(VSS) U16.E9(VSS) U16.G1(VSS) U16.H9(VSS_H1) U16.K1(VSS) U16.K9(VSS) U16.N1(VSS) U91.3(GND) ; also on sheet 8 9 10 11 12 13 15 16 19 20 21 26 27 28 29 30 31 32 33 34 35 36 37 38 39 40 41 42 43 44 45 46 47 48 49 50 51 52 53 54 55 56 58
VCCBAT: C1237.2 U8.CB40(VCCBAT) ; also on sheet 52
CXL_PERSTn: U12.2(A) ; also on sheet 31 34 36
DDR4_COMP_A0: U15.L3(A0) U16.L3(A0) ; also on sheet 19 26 27
DDR4_COMP_A1: U15.L7(A1) U16.L7(A1) ; also on sheet 19 26 27
DDR4_COMP_A2: U15.M3(A2) U16.M3(A2) ; also on sheet 19 26 27
DDR4_COMP_A3: U15.K7(A3) U16.K7(A3) ; also on sheet 19 26 27
DDR4_COMP_A4: U15.K3(A4) U16.K3(A4) ; also on sheet 19 26 27
DDR4_COMP_A5: U15.L8(A5) U16.L8(A5) ; also on sheet 19 26 27
DDR4_COMP_A6: U15.L2(A6) U16.L2(A6) ; also on sheet 19 26 27
DDR4_COMP_A7: U15.M8(A7) U16.M8(A7) ; also on sheet 19 26 27
DDR4_COMP_A8: U15.M2(A8) U16.M2(A8) ; also on sheet 19 26 27
DDR4_COMP_A9: U15.M7(A9) U16.M7(A9) ; also on sheet 19 26 27
DDR4_COMP_A10: U15.J3(A10/AP) U16.J3(A10/AP) ; also on sheet 19 26 27
DDR4_COMP_A11: U15.N2(A11) U16.N2(A11) ; also on sheet 19 26 27
DDR4_COMP_A12: U15.J7(A12/BC_N) U16.J7(A12/BC_N) ; also on sheet 19 26 27
DDR4_COMP_A13: U15.N8(A13) U16.N8(A13) ; also on sheet 19 26 27
DDR4_COMP_A14: U15.H2(WE_N/A14) U16.H2(WE_N/A14) ; also on sheet 19 26 27
DDR4_COMP_A15: U15.H7(CAS_N/A15) U16.H7(CAS_N/A15) ; also on sheet 19 26 27
DDR4_COMP_A16: U15.H8(RAS_N/A16) U16.H8(RAS_N/A16) ; also on sheet 19 26 27
DDR4_COMP_ACT_N: U15.H3(ACT_N) U16.H3(ACT_N) ; also on sheet 19 26 27
DDR4_COMP_ALERT_N: U15.L9(ALERT_N) U16.L9(ALERT_N) ; also on sheet 19 26 27
DDR4_COMP_BA0: U15.K2(BA0) U16.K2(BA0) ; also on sheet 19 26 27
DDR4_COMP_BA1: U15.K8(BA1) U16.K8(BA1) ; also on sheet 19 26 27
DDR4_COMP_BG0: U15.J2(BG0) U16.J2(BG0) ; also on sheet 19 26 27
DDR4_COMP_BG1: U15.J8(BG1) U16.J8(BG1) ; also on sheet 19 26 27
DDR4_COMP_CK_N: U15.F8(CK_C) U16.F8(CK_C) ; also on sheet 19 26 27
DDR4_COMP_CK_P: U15.F7(CK_T) U16.F7(CK_T) ; also on sheet 19 26 27
DDR4_COMP_CKE: U15.G3(CKE) U16.G3(CKE) ; also on sheet 19 26 27
DDR4_COMP_CS_N: U15.G7(CS_N) U16.G7(CS_N) ; also on sheet 19 26 27
DDR4_COMP_DBI_N1: U16.A7(NF/DM_N/DBI_N/TDQS_T) ; also on sheet 19
DDR4_COMP_DBI_N4: U15.A7(NF/DM_N/DBI_N/TDQS_T) ; also on sheet 19
DDR4_COMP_DQ8: U16.C2(DQ0) ; also on sheet 19
DDR4_COMP_DQ9: U16.B7(DQ1) ; also on sheet 19
DDR4_COMP_DQ10: U16.D3(DQ2) ; also on sheet 19
DDR4_COMP_DQ11: U16.D7(DQ3) ; also on sheet 19
DDR4_COMP_DQ12: U16.D2(DQ4) ; also on sheet 19
DDR4_COMP_DQ13: U16.D8(DQ5) ; also on sheet 19
DDR4_COMP_DQ14: U16.E3(DQ6) ; also on sheet 19
DDR4_COMP_DQ15: U16.E7(DQ7) ; also on sheet 19
DDR4_COMP_DQ32: U15.C2(DQ0) ; also on sheet 19
DDR4_COMP_DQ33: U15.B7(DQ1) ; also on sheet 19
DDR4_COMP_DQ34: U15.D3(DQ2) ; also on sheet 19
DDR4_COMP_DQ35: U15.D7(DQ3) ; also on sheet 19
DDR4_COMP_DQ36: U15.D2(DQ4) ; also on sheet 19
DDR4_COMP_DQ37: U15.D8(DQ5) ; also on sheet 19
DDR4_COMP_DQ38: U15.E3(DQ6) ; also on sheet 19
DDR4_COMP_DQ39: U15.E7(DQ7) ; also on sheet 19
DDR4_COMP_DQS_N1: U16.B3(DQS_C) ; also on sheet 19
DDR4_COMP_DQS_N4: U15.B3(DQS_C) ; also on sheet 19
DDR4_COMP_DQS_P1: U16.C3(DQS_T) ; also on sheet 19
DDR4_COMP_DQS_P4: U15.C3(DQS_T) ; also on sheet 19
DDR4_COMP_ODT: U15.F3(ODT) U16.F3(ODT) ; also on sheet 19 26 27
DDR4_COMP_PAR: U15.N3(PAR) U16.N3(PAR) ; also on sheet 19 26 27
DDR4_COMP_RESET_N: U15.L1(RESET_N) U16.L1(RESET_N) ; also on sheet 19 26 27
DDR4_COMP_TEN: U15.G9(TEN/NF) U16.G9(TEN/NF) ; also on sheet 26 27
FPGA_CXL_PERSTN: R126.1 R127.2 U8.BR43(I_PIN_PERST_N_12C_GXF)
FPGA_GNDSENSE: C122.1 U8.BC19(GNDSENSE) ; also on sheet 42
FPGA_TEMP3n: U8.CA11(TEMPDIODE4N) ; also on sheet 34
FPGA_TEMP3p: U8.CB12(TEMPDIODE4P) ; also on sheet 34
FPGA_TEMP4n: U8.AJ45(TEMPDIODE3N) ; also on sheet 34
FPGA_TEMP4p: U8.AG45(TEMPDIODE3P) ; also on sheet 34
FPGA_TEMPDIODE0CN: U8.AE43(TEMPDIODE0CN) ; also on sheet 34
FPGA_TEMPDIODE0CP: U8.AC43(TEMPDIODE0CP) ; also on sheet 34
FPGA_VCC: FB2.2 U8.AC19(VCCL_HPS) U8.AD18(VCCL_HPS) U8.AE19(VCCL_HPS) U8.AF18(VCCL_HPS) U8.AG19(VCCL_HPS) U8.AG21(VCCP) U8.AG23(VCCP) U8.AG25(VCCP) U8.AG27(VCCP) U8.AG31(VCCP) U8.AG33(VCCP) U8.AG35(VCCP) U8.AG37(VCCP) U8.AG39(VCC) U8.AH38(VCC) U8.AH40(VCC) U8.AJ17(VCC) U8.AJ19(VCC) U8.AJ21(VCCP) U8.AJ23(VCCP) U8.AJ25(VCCP) U8.AJ27(VCCP) U8.AJ31(VCCP) U8.AJ33(VCCP) U8.AJ35(VCCP) U8.AJ37(VCCP) U8.AJ39(VCC) U8.AK18(VCC) U8.AK22(VCC) U8.AK24(VCC) U8.AK28(VCC) U8.AK30(VCC) U8.AK34(VCC) U8.AK36(VCC) U8.AK40(VCC) U8.AL17(VCC) U8.AL19(VCC) U8.AL23(VCC) U8.AL25(VCC) U8.AL29(VCC) U8.AL31(VCC) U8.AL35(VCC) U8.AL37(VCC) U8.AM18(VCC) U8.AM20(VCC) U8.AM24(VCC) U8.AM26(VCC) U8.AM30(VCC) U8.AM32(VCC) U8.AM36(VCC) U8.AM38(VCC) U8.AN19(VCC) U8.AN21(VCC) U8.AN25(VCC) U8.AN27(VCC) U8.AN31(VCC) U8.AN33(VCC) U8.AN37(VCC) U8.AN39(VCC) U8.AP20(VCC) U8.AP22(VCC) U8.AP26(VCC) U8.AP28(VCC) U8.AP32(VCC) U8.AP34(VCC) U8.AP38(VCC) U8.AR17(VCC) U8.AR21(VCC) U8.AR23(VCC) U8.AR25(VCC) U8.AR27(VCC) U8.AR29(VCC) U8.AR31(VCC) U8.AR33(VCC) U8.AR35(VCC) U8.AR39(VCC) U8.AT18(VCC) U8.AT22(VCC) U8.AT34(VCC) U8.AT36(VCC) U8.AU17(VCC) U8.AU19(VCC) U8.AU35(VCC) U8.AU37(VCC) U8.AV18(VCC) U8.AV20(VCC) U8.AV22(VCC) U8.AV34(VCC) U8.AV36(VCC) U8.AV38(VCC) U8.AW19(VCC) U8.AW21(VCC) U8.AW37(VCC) U8.AW39(VCC) U8.AY20(VCC) U8.AY22(VCC) U8.AY34(VCC) U8.AY38(VCC) U8.BA17(VCC) U8.BA21(VCC) U8.BA35(VCC) U8.BA39(VCC) U8.BB18(VCC) U8.BB22(VCC) U8.BB34(VCC) U8.BB36(VCC) U8.BC17(VCC) U8.BC35(VCC) U8.BC37(VCC) U8.BD18(VCC) U8.BD20(VCC) U8.BD22(VCC) U8.BD34(VCC) U8.BD36(VCC) U8.BD38(VCC) U8.BE21(VCC) U8.BE37(VCC) U8.BE39(VCC) U8.BF20(VCC) U8.BF22(VCC) U8.BF34(VCC) U8.BF38(VCC) U8.BG17(VCC) U8.BG21(VCC) U8.BG35(VCC) U8.BG39(VCC) U8.BH18(VCC) U8.BH22(VCC) U8.BH34(VCC) U8.BH36(VCC) U8.BJ17(VCC) U8.BJ19(VCC) U8.BJ35(VCC) U8.BJ37(VCC) U8.BK18(VCC) U8.BK20(VCC) U8.BK22(VCC) U8.BK34(VCC) U8.BK36(VCC) U8.BK38(VCC) U8.BK40(VCC) U8.BL19(VCC) U8.BL21(VCC) U8.BL37(VCC) U8.BL39(VCC) U8.BM20(VCC) U8.BM22(VCC) U8.BM34(VCC) U8.BM38(VCC) U8.BM40(VCC) U8.BN17(VCC) U8.BN21(VCC) U8.BN35(VCC) U8.BN39(VCC) U8.BP18(VCC) U8.BP22(VCC) U8.BP34(VCC) U8.BP36(VCC) U8.BP40(VCC) U8.BR17(VCC) U8.BR19(VCC) U8.BR23(VCC) U8.BR25(VCC) U8.BR27(VCC) U8.BR29(VCC) U8.BR31(VCC) U8.BR33(VCC) U8.BR35(VCC) U8.BR37(VCC) U8.BT18(VCC) U8.BT20(VCC) U8.BT24(VCC) U8.BT26(VCC) U8.BT30(VCC) U8.BT32(VCC) U8.BT36(VCC) U8.BT38(VCC) U8.BU19(VCC) U8.BU21(VCC) U8.BU25(VCC) U8.BU27(VCC) U8.BU31(VCC) U8.BU33(VCC) U8.BU37(VCC) U8.BU39(VCC) U8.BV20(VCC) U8.BV22(VCC) U8.BV26(VCC) U8.BV28(VCC) U8.BV32(VCC) U8.BV34(VCC) U8.BV38(VCC) U8.BV40(VCC) U8.BW17(VCC) U8.BW21(VCC) U8.BW23(VCC) U8.BW27(VCC) U8.BW29(VCC) U8.BW33(VCC) U8.BW35(VCC) U8.BW39(VCC) U8.BY18(VCC) U8.BY22(VCC) U8.BY24(VCC) U8.BY28(VCC) U8.BY30(VCC) U8.BY34(VCC) U8.BY36(VCC) U8.BY40(VCC) U8.CA17(VCC) U8.CA19(VCCP) U8.CA21(VCCP) U8.CA23(VCCP) U8.CA25(VCCP) U8.CA27(VCCP) U8.CA29(VCCP) U8.CA31(VCCP) U8.CA33(VCCP) U8.CA35(VCC) U8.CA37(VCC) U8.CB36(VCC) U8.CC19(VCCP) U8.CC21(VCCP) U8.CC23(VCCP) U8.CC25(VCCP) U8.CC27(VCCP) U8.CC29(VCCP) U8.CC31(VCCP) U8.CC33(VCCP) ; also on sheet 39 42 43 44 45 46
FPGA_VCC_HSSI_GXF: FB3.2 U8.AH42(VCC_HSSI_GXFL_12C) U8.AJ41(VCC_HSSI_GXFL_12C) U8.AK42(VCC_HSSI_GXFL_12C) U8.AL41(VCC_HSSI_GXFL_12C) U8.AM42(VCC_HSSI_GXFL_12C) U8.AN41(VCC_HSSI_GXFL_12C) U8.AP40(VCCH) U8.AP42(VCC_HSSI_GXFL_12C) U8.AR41(VCC_HSSI_GXFL_12C) U8.AT42(VCC_HSSI_GXFL_12C) U8.AU41(VCC_HSSI_GXFL_12C) U8.AV40(VCCH) U8.AV42(VCC_HSSI_GXFL_12C) U8.AW41(VCC_HSSI_GXFL_12C) U8.AY14(VCC_HSSI_GXFR_13A) U8.AY42(VCC_HSSI_GXFL_12C) U8.BA15(VCC_HSSI_GXFR_13A) U8.BA41(VCC_HSSI_GXFL_12C) U8.BB14(VCC_HSSI_GXFR_13A) U8.BB40(VCCH) U8.BB42(VCC_HSSI_GXFL_12C) U8.BC15(VCC_HSSI_GXFR_13A) U8.BC41(VCC_HSSI_GXFL_12C) U8.BD14(VCC_HSSI_GXFR_13A) U8.BD16(VCCH) U8.BD42(VCC_HSSI_GXFL_12C) U8.BE15(VCC_HSSI_GXFR_13A) U8.BE41(VCC_HSSI_GXFL_12C) U8.BF14(VCC_HSSI_GXFR_13A) U8.BF40(VCCH) U8.BF42(VCC_HSSI_GXFL_12C) U8.BG15(VCC_HSSI_GXFR_13A) U8.BG41(VCC_HSSI_GXFL_12C) U8.BH14(VCC_HSSI_GXFR_13A) U8.BH16(VCCH) U8.BH42(VCC_HSSI_GXFL_12C) U8.BJ15(VCC_HSSI_GXFR_13A) U8.BJ41(VCC_HSSI_GXFL_12C) U8.BK14(VCC_HSSI_GXFR_13A) U8.BK42(VCC_HSSI_GXFL_12C) U8.BL15(VCC_HSSI_GXFR_13A) U8.BL41(VCC_HSSI_GXFL_12C) U8.BM14(VCC_HSSI_GXFR_13A) U8.BM16(VCCH) U8.BN15(VCC_HSSI_GXFR_13A) U8.BP14(VCC_HSSI_GXFR_13A) U8.BR15(VCC_HSSI_GXFR_13A) U8.BT14(VCC_HSSI_GXFR_13A) U8.BT16(VCCH) U8.BU15(VCC_HSSI_GXFR_13A) U8.BV14(VCC_HSSI_GXFR_13A) U8.BW15(VCC_HSSI_GXFR_13A) U8.BY14(VCC_HSSI_GXFR_13A) U8.CA15(VCC_HSSI_GXFR_13A) U8.CB14(VCC_HSSI_GXFR_13A) U8.CC15(VCC_HSSI_GXFR_13A) U8.CC37(VCCL_SDM) U8.CD38(VCCL_SDM) U8.CE37(VCCL_SDM) U8.CF38(VCCL_SDM) ; also on sheet 39 47
FPGA_VCCA_PLL: C123.2 C124.1 C125.1 FB7.1 U8.AA23(VCCA_PLL) U8.AA27(VCCA_PLL) U8.AA31(VCCA_PLL) U8.AA35(VCCA_PLL) U8.CJ21(VCCA_PLL) U8.CJ25(VCCA_PLL) U8.CJ29(VCCA_PLL) U8.CJ33(VCCA_PLL) ; also on sheet 39
FPGA_VCCCLK_GXF: C107.2 C112.2 C113.2 C114.2 C115.2 C119.1 C120.1 C121.2 C1026.2 FB5.1 R119.2 R126.2 R841.2 U8.AW11(VCCCLK_GXFR_13A) U8.AY10(VCCCLK_GXFR_13A) U8.BM46(VCCCLK_GXFL_12C) U8.BN45(VCCCLK_GXFL_12C) U12.5(VCC) U91.5(VCC) ; also on sheet 39
FPGA_VCCERT_FGT_GXF: U8.AN43(VCCERT_FGT_GXFL_12C) U8.AP44(VCCERT_FGT_GXFL_12C) U8.AT44(VCCERT_FGT_GXFL_12C) U8.AU43(VCCERT_FGT_GXFL_12C) U8.AV44(VCCERT_FGT_GXFL_12C) U8.AY44(VCCERT_FGT_GXFL_12C) U8.BA13(VCCERT_FGT_GXFR_13A) U8.BA43(VCCERT_FGT_GXFL_12C) U8.BB12(VCCERT_FGT_GXFR_13A) U8.BB44(VCCERT_FGT_GXFL_12C) U8.BD12(VCCERT_FGT_GXFR_13A) U8.BD44(VCCERT_FGT_GXFL_12C) U8.BE13(VCCERT_FGT_GXFR_13A) U8.BE43(VCCERT_FGT_GXFL_12C) U8.BF12(VCCERT_FGT_GXFR_13A) U8.BF44(VCCERT_FGT_GXFL_12C) U8.BH12(VCCERT_FGT_GXFR_13A) U8.BH44(VCCERT_FGT_GXFL_12C) U8.BJ13(VCCERT_FGT_GXFR_13A) U8.BJ43(VCCERT_FGT_GXFL_12C) U8.BK12(VCCERT_FGT_GXFR_13A) U8.BK44(VCCERT_FGT_GXFL_12C) U8.BM12(VCCERT_FGT_GXFR_13A) U8.BN13(VCCERT_FGT_GXFR_13A) U8.BP12(VCCERT_FGT_GXFR_13A) U8.BT12(VCCERT_FGT_GXFR_13A) U8.BU13(VCCERT_FGT_GXFR_13A) U8.BV12(VCCERT_FGT_GXFR_13A) ; also on sheet 39 49
FPGA_VCCFUSEWR_GXF: U8.AW13(VCCFUSECORE_GXFR_13A) U8.AY12(VCCFUSEWR_GXFR_13A) U8.BM44(VCCFUSEWR_GXFL_12C) U8.BN43(VCCFUSECORE_GXFL_12C) ; also on sheet 39 51
FPGA_VCCH_FGT_GXF: C126.1 C127.1 C128.2 FB6.1 FB8.1 U8.AN45(VCCH_FGT_GXFL_12C) U8.AP46(VCCH_FGT_GXFL_12C) U8.AT46(VCCH_FGT_GXFL_12C) U8.AU45(VCCH_FGT_GXFL_12C) U8.AV46(VCCH_FGT_GXFL_12C) U8.AY46(VCCH_FGT_GXFL_12C) U8.BA11(VCCH_FGT_GXFR_13A) U8.BA45(VCCH_FGT_GXFL_12C) U8.BB10(VCCH_FGT_GXFR_13A) U8.BB46(VCCH_FGT_GXFL_12C) U8.BD10(VCCH_FGT_GXFR_13A) U8.BD46(VCCH_FGT_GXFL_12C) U8.BE11(VCCH_FGT_GXFR_13A) U8.BE45(VCCH_FGT_GXFL_12C) U8.BF10(VCCH_FGT_GXFR_13A) U8.BF46(VCCH_FGT_GXFL_12C) U8.BH10(VCCH_FGT_GXFR_13A) U8.BH46(VCCH_FGT_GXFL_12C) U8.BJ11(VCCH_FGT_GXFR_13A) U8.BJ45(VCCH_FGT_GXFL_12C) U8.BK10(VCCH_FGT_GXFR_13A) U8.BK46(VCCH_FGT_GXFL_12C) U8.BM10(VCCH_FGT_GXFR_13A) U8.BN11(VCCH_FGT_GXFR_13A) U8.BP10(VCCH_FGT_GXFR_13A) U8.BT10(VCCH_FGT_GXFR_13A) U8.BU11(VCCH_FGT_GXFR_13A) U8.BV10(VCCH_FGT_GXFR_13A) ; also on sheet 39
FPGA_VCCH_SDM: U8.CE39(VCCH_SDM) ; also on sheet 39 48
FPGA_VCCIO_1V2: C205.1 C206.1 C207.1 C208.1 C209.1 C210.1 C211.1 C212.1 C213.1 C214.1 C215.1 C216.1 C217.1 C218.1 C219.1 C220.1 C221.1 C222.2 C223.2 C224.1 C225.1 C226.1 C227.1 C228.1 C229.1 C230.1 C231.1 C232.1 C233.1 C234.1 C235.1 C236.1 C237.1 C238.1 C239.1 C240.1 C241.1 C242.1 U8.AC21(VCCIO_PIO_3D) U8.AC23(VCCIO_PIO_3D) U8.AC35(VCCIO_PIO_3A) U8.AC37(VCCIO_PIO_3A) U8.AE21(VCCIO_PIO_3D) U8.AE23(VCCIO_PIO_3D) U8.AE35(VCCIO_PIO_3A) U8.AE37(VCCIO_PIO_3A) U8.CC39(VCCIO_PIO_SDM) U8.CE19(VCCIO_PIO_2D) U8.CE21(VCCIO_PIO_2D) U8.CE23(VCCIO_PIO_2C) U8.CE25(VCCIO_PIO_2C) U8.CE27(VCCIO_PIO_2F) U8.CE29(VCCIO_PIO_2F) U8.CE31(VCCIO_PIO_2E) U8.CE33(VCCIO_PIO_2E) U8.CG19(VCCIO_PIO_2D) U8.CG21(VCCIO_PIO_2D) U8.CG23(VCCIO_PIO_2C) U8.CG25(VCCIO_PIO_2C) U8.CG27(VCCIO_PIO_2F) U8.CG29(VCCIO_PIO_2F) U8.CG31(VCCIO_PIO_2E) U8.CG33(VCCIO_PIO_2E) U15.A1(VDD) U15.B2(VDDQ) U15.B8(VDDQ) U15.C1(VDDQ) U15.C7(VDD) U15.C9(VDDQ) U15.E2(VDDQ) U15.E8(VDDQ) U15.F1(VDD) U15.F9(VDD) U15.H1(VDD) U15.J9(VDD) U15.M1(VDD) U15.N9(VDD) U16.A1(VDD) U16.B2(VDDQ) U16.B8(VDDQ) U16.C1(VDDQ) U16.C7(VDD) U16.C9(VDDQ) U16.E2(VDDQ) U16.E8(VDDQ) U16.F1(VDD) U16.F9(VDD) U16.H1(VDD) U16.J9(VDD) U16.M1(VDD) U16.N9(VDD) ; also on sheet 10 16 26 27 31 34 35 36 39 50 54 55 56
FPGA_VCCIO_SDM_HPS: U8.AC17(VCCIO_HPS) U8.AE17(VCCIO_HPS) U8.AG17(VCCIO_HPS) U8.CG37(VCCIO_SDM) U8.CG41(VCCFUSEWR_SDM) U8.CJ41(VCCFUSEWR_SDM) ; also on sheet 11 28 33 35 39 52 53
FPGA_VCCLSENSE: C122.2 U8.BE19(VCCLSENSE) ; also on sheet 42
FPGA_VCCPLL: C116.1 C117.1 C118.2 FB4.1 U8.AH16(VCCPLL_HPS) U8.CC41(VCCADC) U8.CF40(VCCPLL_SDM) ; also on sheet 39
FPGA_VCCPLLDIG_HPS: C108.2 C109.1 FB2.1 U8.AF16(VCCPLLDIG_HPS) ; also on sheet 39
FPGA_VCCPLLDIG_SDM: C110.2 C111.1 FB3.1 U8.CG39(VCCPLLDIG_SDM) ; also on sheet 39
FPGA_VCCPT: FB4.2 FB5.2 FB6.2 FB8.2 U8.AF22(VCCPT) U8.AF26(VCCPT) U8.AF30(VCCPT) U8.AF34(VCCPT) U8.CD20(VCCPT) U8.CD24(VCCPT) U8.CD28(VCCPT) U8.CD32(VCCPT) ; also on sheet 28 39 50 51
FPGA_VCCR_CORE: FB7.2 U8.AH20(VCCRCORE) U8.AH24(VCCRCORE) U8.AH28(VCCRCORE) U8.AH32(VCCRCORE) U8.AH36(VCCRCORE) U8.CB18(VCCRCORE) U8.CB22(VCCRCORE) U8.CB26(VCCRCORE) U8.CB30(VCCRCORE) U8.CB34(VCCRCORE) ; also on sheet 39 49
GFX_1ST_PERSTN: R840.1 U91.2(A) ; also on sheet 10
GXF_2ND_PERSTn: R119.1 U8.CN11(IO_PLL_REFCLK_13A_GXF) ; also on sheet 10 34 36
HPS_CON_GPIO26: U8.AF8(HPS_IOB_3,_GPIO1_IO2,_SPIM1_MISO,_UART0_TX,_I2C0_SDA,_NAND_WE_N,_EMAC1_RX_CLK) ; also on sheet 28
HPS_CON_GPIO27: U8.AT12(HPS_IOB_4,_GPIO1_IO3,_SPIM1_SS0_N,_UART0_RX,_I2C0_SCL,_NAND_RE_N,_EMAC1_RX_CTL) ; also on sheet 28
HPS_GPIO0: U8.AC15(HPS_IOA_1,_GPIO0_IO0,_SPIM0_SS1_N,_SPIS0_CLK,_UART0_CTS_N,_NAND_ADQ0,_USB0_CLK,_SDMMC_CCLK) ; also on sheet 28
HPS_GPIO1: U8.AL15(HPS_IOA_2,_GPIO0_IO1,_SPIM1_SS1_N,_SPIS0_MOSI,_UART0_RTS_N,_NAND_ADQ1,_USB0_STP,_SDMMC_CMD) ; also on sheet 28
HPS_GPIO2: U8.AJ11(HPS_IOA_3,_GPIO0_IO2,_SPIS0_SS0_N,_UART0_TX,_I2C1_SDA,_NAND_WE_N,_USB0_DIR,_SDMMC_DATA0) ; also on sheet 28
HPS_GPIO3: U8.AM16(HPS_IOA_4,_GPIO0_IO3,_SPIS0_MISO,_UART0_RX,_I2C1_SCL,_NAND_RE_N,_USB0_DATA0,_SDMMC_DATA1) ; also on sheet 28
HPS_GPIO4: U8.AH12(HPS_IOA_5,_GPIO0_IO4,_SPIM0_CLK,_UART1_CTS_N,_I2C0_SDA,_NAND_WP_N,_USB0_DATA1,_SDMMC_DATA2) ; also on sheet 28
HPS_GPIO5: U8.AN15(HPS_IOA_6,_GPIO0_IO5,_SPIM0_MOSI,_UART1_RTS_N,_I2C0_SCL,_NAND_ADQ2,_USB0_NXT,_SDMMC_DATA3) ; also on sheet 28
HPS_GPIO6: U8.AG13(HPS_IOA_7,_GPIO0_IO6,_SPIM0_MISO,_MDIO2_MDIO,_UART1_TX,_I2C_EMAC2_SDA,_NAND_ADQ3,_USB0_DATA2,_SDMMC_DATA4) ; also on sheet 28
HPS_GPIO7: U8.AP16(HPS_IOA_8,_GPIO0_IO7,_SPIM0_SS0_N,_MDIO2_MDC,_UART1_RX,_I2C_EMAC2_SCL,_NAND_CLE,_USB0_DATA3,_SDMMC_DATA5) ; also on sheet 28
HPS_GPIO8: U8.AF14(HPS_IOA_9,_GPIO0_IO8,_SPIM1_CLK,_SPIS1_CLK,_MDIO1_MDIO,_I2C_EMAC1_SDA,_NAND_ADQ4,_USB0_DATA4,_SDMMC_DATA6) ; also on sheet 28
HPS_GPIO9: U8.AT16(HPS_IOA_10,_GPIO0_IO9,_SPIM1_MOSI,_SPIS1_MOSI,_MDIO1_MDC,_I2C_EMAC1_SCL,_NAND_ADQ5,_USB0_DATA5,_SDMMC_DATA7) ; also on sheet 28
HPS_GPIO10: U8.AH10(HPS_IOA_11,_GPIO0_IO10,_SPIM1_MISO,_SPIS1_SS0_N,_MDIO0_MDIO,_I2C_EMAC0_SDA,_NAND_ADQ6,_USB0_DATA6) ; also on sheet 28
HPS_GPIO11: U8.AU15(HPS_IOA_12,_GPIO0_IO11,_SPIM1_SS0_N,_SPIS1_MISO,_MDIO0_MDC,_I2C_EMAC0_SCL,_NAND_ADQ7,_USB0_DATA7) ; also on sheet 28
HPS_GPIO12: U8.AJ7(HPS_IOA_13,_GPIO0_IO12,_NAND_ALE,_USB1_CLK,_EMAC0_TX_CLK) ; also on sheet 28
HPS_GPIO13: U8.AL13(HPS_IOA_14,_GPIO0_IO13,_NAND_RB,_USB1_STP,_EMAC0_TX_CTL) ; also on sheet 28
HPS_GPIO14: U8.AH8(HPS_IOA_15,_GPIO0_IO14,_NAND_CE_N,_USB1_DIR,_EMAC0_RX_CLK) ; also on sheet 28
HPS_GPIO15: U8.AM14(HPS_IOA_16,_GPIO0_IO15,_USB1_DATA0,_EMAC0_RX_CTL) ; also on sheet 28
HPS_GPIO16: U8.AD14(HPS_IOA_17,_GPIO0_IO16,_NAND_ADQ8,_USB1_DATA1,_EMAC0_TXD0) ; also on sheet 28
HPS_GPIO17: U8.AN13(HPS_IOA_18,_GPIO0_IO17,_NAND_ADQ9,_USB1_NXT,_EMAC0_TXD1) ; also on sheet 28
HPS_GPIO18: U8.AG11(HPS_IOA_19,_GPIO0_IO18,_NAND_ADQ10,_USB1_DATA2,_EMAC0_RXD0) ; also on sheet 28
HPS_GPIO19: U8.AP14(HPS_IOA_20,_GPIO0_IO19,_SPIM1_SS1_N,_NAND_ADQ11,_USB1_DATA3,_EMAC0_RXD1) ; also on sheet 28
HPS_GPIO20: U8.AG9(HPS_IOA_21,_GPIO0_IO20,_SPIM1_CLK,_SPIS0_CLK,_UART0_CTS_N,_I2C1_SDA,_NAND_ADQ12,_USB1_DATA4,_EMAC0_TXD2) ; also on sheet 28
HPS_GPIO21: U8.AT14(HPS_IOA_22,_GPIO0_IO21,_SPIM1_MOSI,_SPIS0_MOSI,_UART0_RTS_N,_I2C1_SCL,_NAND_ADQ13,_USB1_DATA5,_EMAC0_TXD3) ; also on sheet 28
HPS_GPIO22: U8.AF12(HPS_IOA_23,_GPIO0_IO22,_SPIM1_MISO,_SPIS0_SS0_N,_UART0_TX,_I2C0_SDA,_NAND_ADQ14,_USB1_DATA6,_EMAC0_RXD2) ; also on sheet 28
HPS_GPIO23: U8.AU13(HPS_IOA_24,_GPIO0_IO23,_SPIM1_SS0_N,_SPIS0_MISO,_UART0_RX,_I2C0_SCL,_NAND_ADQ15,_USB1_DATA7,_EMAC0_RXD3) ; also on sheet 28
HPS_GPIO24: U8.AF10(HPS_IOB_1,_GPIO1_IO0,_SPIM1_CLK,_UART0_CTS_N,_NAND_ADQ0,_EMAC1_TX_CLK) ; also on sheet 28
HPS_GPIO25: U8.AU11(HPS_IOB_2,_GPIO1_IO1,_SPIM1_MOSI,_UART0_RTS_N,_NAND_ADQ1,_EMAC1_TX_CTL) ; also on sheet 28
HPS_GPIO28: U8.AG7(HPS_IOB_5,_GPIO1_IO4,_SPIM1_SS1_N,_SPIS1_CLK,_UART1_CTS_N,_NAND_WP_N,_EMAC1_TXD0) ; also on sheet 28
HPS_GPIO29: U8.AP12(HPS_IOB_6,_GPIO1_IO5,_SPIS1_MOSI,_UART1_RTS_N,_NAND_ADQ2,_EMAC1_TXD1) ; also on sheet 28
HPS_GPIO30: U8.AC13(HPS_IOB_7,_GPIO1_IO6,_SPIS1_SS0_N,_UART1_TX,_I2C1_SDA,_NAND_ADQ3,_EMAC1_RXD0) ; also on sheet 28
HPS_GPIO31: U8.AN11(HPS_IOB_8,_GPIO1_IO7,_SPIS1_MISO,_UART1_RX,_I2C1_SCL,_NAND_CLE,_EMAC1_RXD1) ; also on sheet 28
HPS_GPIO32: U8.AD12(HPS_IOB_9,_GPIO1_IO8,_JTAG_TCK,_SPIS0_CLK,_MDIO2_MDIO,_I2C_EMAC2_SDA,_NAND_ADQ4,_EMAC1_TXD2) ; also on sheet 28
HPS_GPIO33: U8.AM12(HPS_IOB_10,_GPIO1_IO9,_JTAG_TMS,_SPIS0_MOSI,_MDIO2_MDC,_I2C_EMAC2_SCL,_NAND_ADQ5,_EMAC1_TXD3) ; also on sheet 28
HPS_GPIO34: U8.AD10(HPS_IOB_11,_GPIO1_IO10,_JTAG_TDO,_SPIS0_SS0_N,_MDIO0_MDIO,_I2C_EMAC0_SDA,_NAND_ADQ6,_EMAC1_RXD2) ; also on sheet 28
HPS_GPIO35: U8.AL11(HPS_IOB_12,_GPIO1_IO11,_JTAG_TDI,_SPIS0_MISO,_MDIO0_MDC,_I2C_EMAC0_SCL,_NAND_ADQ7,_EMAC1_RXD3) ; also on sheet 28
HPS_GPIO36: U8.AC11(HPS_IOB_13,_GPIO1_IO12,_I2C1_SDA,_NAND_ALE,_SDMMC_DATA0,_EMAC2_TX_CLK) ; also on sheet 28
HPS_GPIO37: U8.AT10(HPS_IOB_14,_GPIO1_IO13,_I2C1_SCL,_NAND_RB,_SDMMC_CMD,_EMAC2_TX_CTL) ; also on sheet 28
HPS_GPIO38: U8.AD8(HPS_IOB_15,_GPIO1_IO14,_UART1_TX,_NAND_CE_N,_SDMMC_CCLK,_EMAC2_RX_CLK) ; also on sheet 28
HPS_GPIO39: U8.AP10(HPS_IOB_16,_GPIO1_IO15,_UART1_RX,_SDMMC_DATA1,_EMAC2_RX_CTL) ; also on sheet 28
HPS_GPIO40: U8.AC9(HPS_IOB_17,_GPIO1_IO16,_UART1_CTS_N,_NAND_ADQ8,_SDMMC_DATA2,_EMAC2_TXD0) ; also on sheet 28
HPS_GPIO41: U8.AM10(HPS_IOB_18,_GPIO1_IO17,_SPIM0_SS1_N,_UART1_RTS_N,_NAND_ADQ9,_SDMMC_DATA3,_EMAC2_TXD1) ; also on sheet 28
HPS_GPIO42: U8.AB10(HPS_IOB_19,_GPIO1_IO18,_SPIM0_MISO,_MDIO1_MDIO,_I2C_EMAC1_SDA,_NAND_ADQ10,_SDMMC_DATA4,_EMAC2_RXD0) ; also on sheet 28
HPS_GPIO43: U8.AJ13(HPS_IOB_20,_GPIO1_IO19,_SPIM0_SS0_N,_MDIO1_MDC,_I2C_EMAC1_SCL,_NAND_ADQ11,_SDMMC_DATA5,_EMAC2_RXD1) ; also on sheet 28
HPS_GPIO44: U8.AB14(HPS_IOB_21,_GPIO1_IO20,_SPIM0_CLK,_SPIS1_CLK,_I2C_EMAC2_SDA,_NAND_ADQ12,_SDMMC_DATA6,_EMAC2_TXD2) ; also on sheet 28
HPS_GPIO45: U8.AH14(HPS_IOB_22,_GPIO1_IO21,_SPIM0_MOSI,_SPIS1_MOSI,_I2C_EMAC2_SCL,_NAND_ADQ13,_SDMMC_DATA7,_EMAC2_TXD3) ; also on sheet 28
HPS_GPIO46: U8.AB12(HPS_IOB_23,_GPIO1_IO22,_SPIM0_MISO,_SPIS1_SS0_N,_MDIO0_MDIO,_I2C_EMAC0_SDA,_NAND_ADQ14,_EMAC2_RXD2) ; also on sheet 28
HPS_GPIO47: U8.AJ9(HPS_IOB_24,_GPIO1_IO23,_SPIM0_SS0_N,_SPIS1_MISO,_MDIO0_MDC,_I2C_EMAC0_SCL,_NAND_ADQ15,_EMAC2_RXD3) ; also on sheet 28
PCIE_PERSTn: R123.2 R841.1 U8.CG13(I_PIN_PERST_N_13A_GXF) ; also on sheet 36
N586023: R124.1 U8.CA7(RCOMP_N_Q2_CH1_FGT_13A_GXF)
N586027: R124.2 U8.BY8(RCOMP_P_Q2_CH1_FGT_13A_GXF)
N586139: R128.1 U8.AM48(RCOMP_N_Q2_CH1_FGT_12C_GXF)
N586147: R128.2 U8.AL49(RCOMP_P_Q2_CH1_FGT_12C_GXF)
N587132: R125.1 U12.1(OE)
N587200: R127.1 U12.4(Y)
N1063403: R163.2 U15.B9(ZQ)
N1070944: R164.2 U16.B9(ZQ)
N5919185: R123.1 U91.4(Y)
N5919260: R839.1 U91.1(OE)

Not connected (* = marked no-connect by the designer): U8 AA17(DNU)* AB16(DNU)* AB42(DNU)* AC41(DNU)* AC47(APROBE_GXF_FGT12C_Q3_CH3)* AD46(APROBE2_GXF_FGT12C_Q3_CH3)* AG15(DNU)* AJ15(DNU)* AK48(APROBE_GXF_FGT12C_Q2_CH3)* BA49(APROBE_GXF_FGT12C_Q0_CH3)* BL7(APROBE_GXF_FGT13A_Q0_CH3)* BR41(DNU)* BT42(DNU)* BT44(DNU)* BW41(IO_PLL_REFCLK_12C_GXF)* BW43(DNU)* CB8(APROBE_GXF_FGT13A_Q2_CH3)* CD12(DNU)* CE13(DNU)* CF14(DNU)* CF42(DNU)* CF50(DNU)* CH16(DNU)* CH42(DNU)* CH50(DNU)* CJ9(APROBE2_GXF_FGT13A_Q3_CH3)* CJ15(DNU)* CK10(APROBE_GXF_FGT13A_Q3_CH3)* CR11(DNU)* CT54(DNU)* CW11(DNU)* DA7(DNU)* DC3(DNU)* DC5(DNU)* DC7(DNU)* DD4(DNU)* DD6(DNU)* J55(NC)* L55(NC)* M54(NC)*; U15 A3(NF/TDQS_C)* F2(C2/ODT1/NC)* G2(C0/CKE1/NC)* G8(C1/CS1_N/NC)* N7(NF)*; U16 A3(NF/TDQS_C)* F2(C2/ODT1/NC)* G2(C0/CKE1/NC)* G8(C1/CS1_N/NC)* N7(NF)*

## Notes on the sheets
sheet 22
- (FM76: NC)
- HPS
- FHT Not Used
- VCC = 0.8V - 3.6V
- Layout Note: place the res under BGA ball
- FHT Not Used
- Pull-up on PG39
- CXL Push Button PERSTn
- VCC = 0.8V - 3.6V
- Layout Note: place the res under BGA ball
sheet 23
- (FM76: NC)
- (FM76: NC)
- (FM76: NC)
- (FM76: NC)
- Unused
  IO Banks
  Can be
  powered
  down
- (FM76: NC)
- (FM76: NC)
- (FM76: NC)
- (FM76: NC)
- (FM76: NC)
- (FM76: NC)
- 0.9V
- 0.8V
- Place filter close to FPGA
- Place caps under FPGA pins
- Filter for:
- VCCPLL_SDM
- VCCPLL_HPS
- 1.2V
- Place filter close to FPGA
sheet 25
- DDR4 COMPONENT #1/#2
